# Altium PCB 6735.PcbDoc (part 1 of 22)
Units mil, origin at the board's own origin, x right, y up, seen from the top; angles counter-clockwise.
Board outline 2641.73 x 5165.35 mil, 6 copper layers (Top, Inner Layer 2, Inner Layer 3, Inner Layer 4, Inner Layer 5, Bottom), stack 35.7 mil thick; 1011 components, 790 nets, 4118 pads, 9325 vias.
Unrouted connection lines stored in the file: 4610.
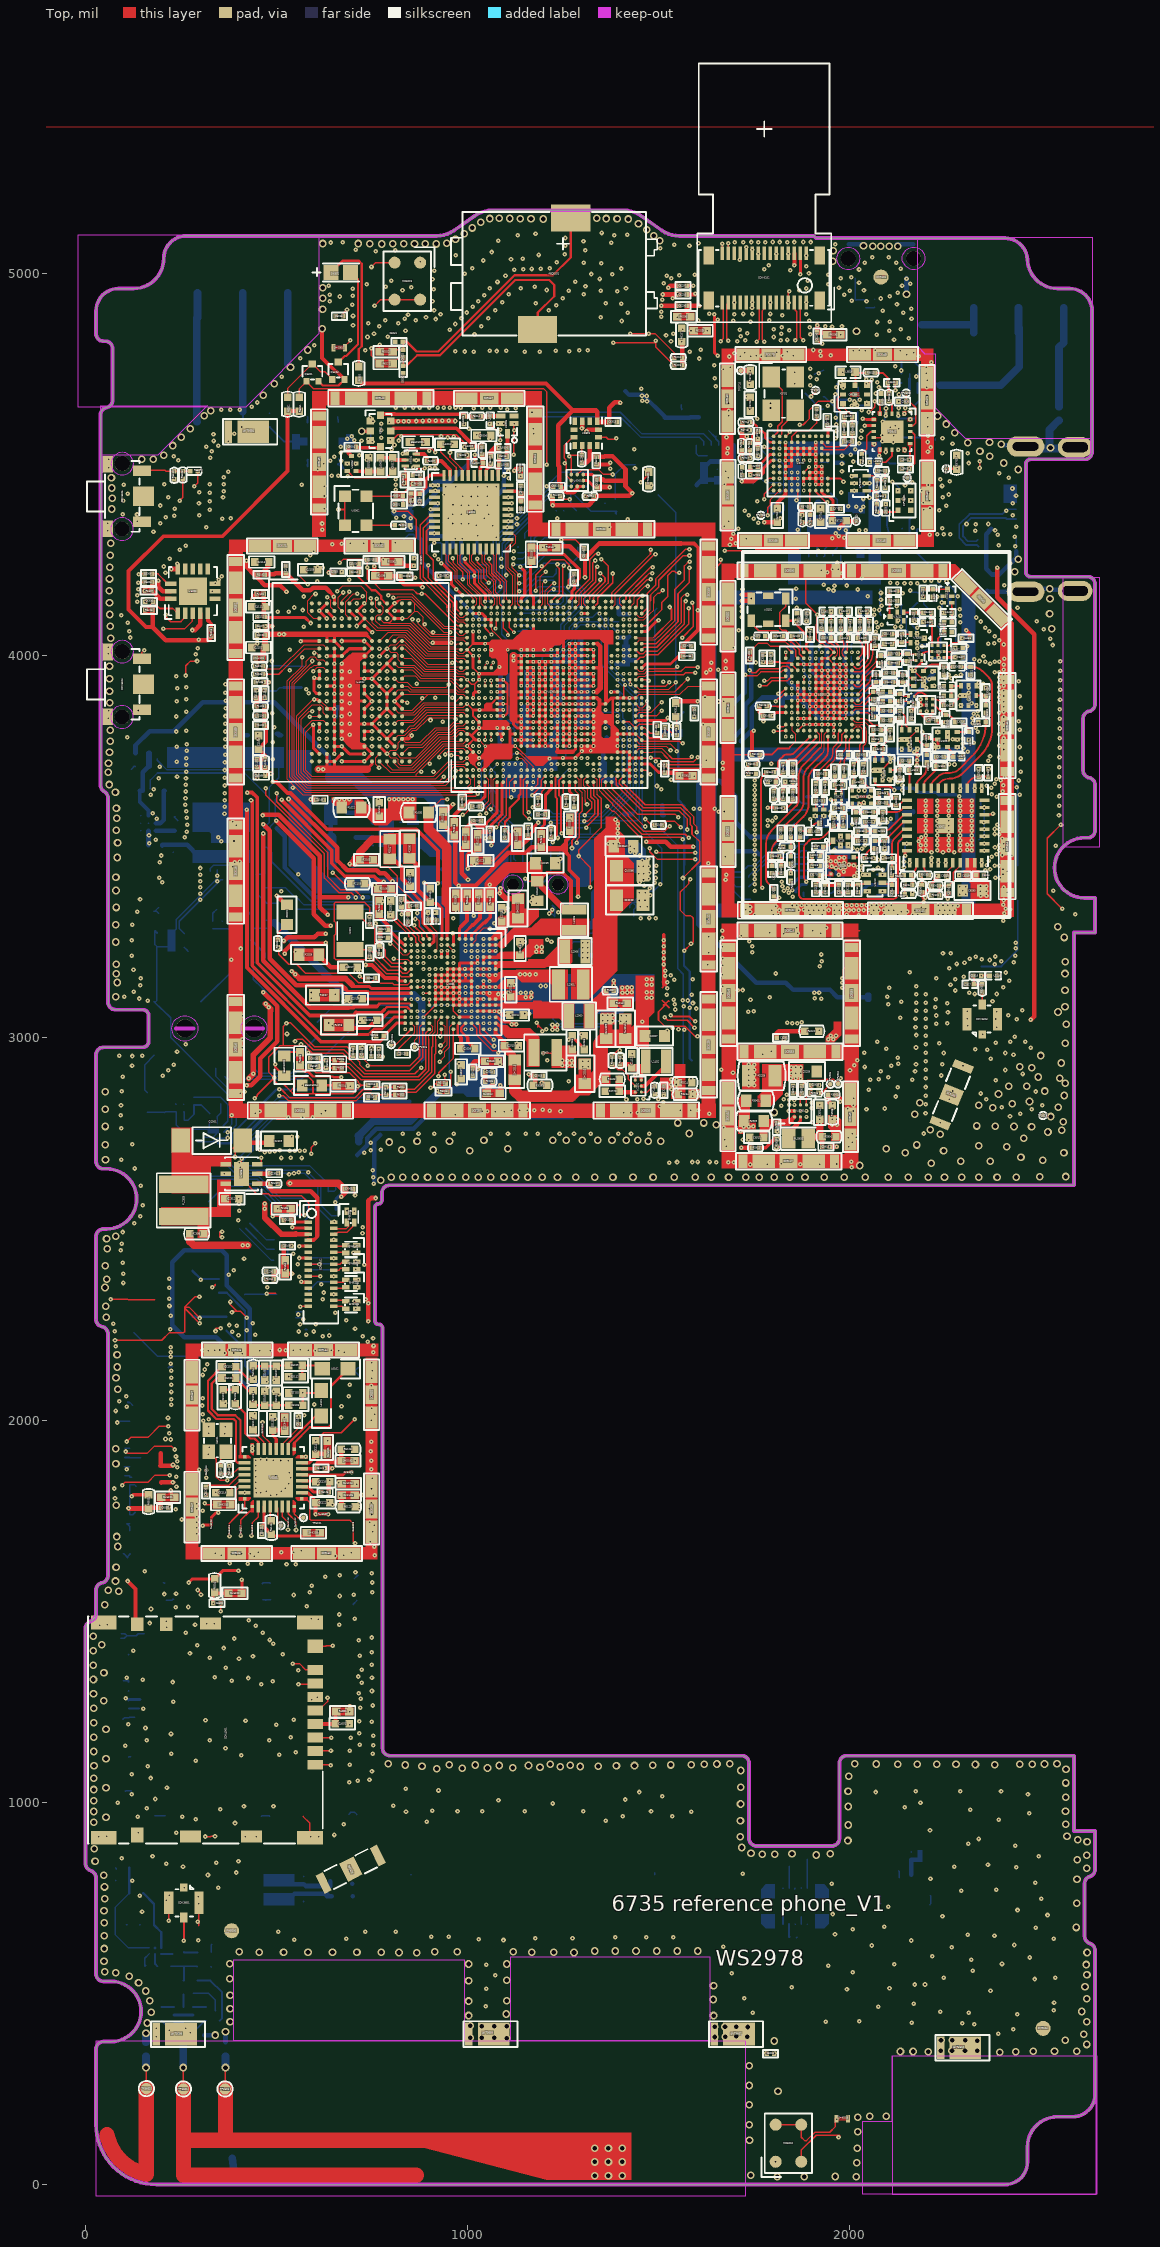
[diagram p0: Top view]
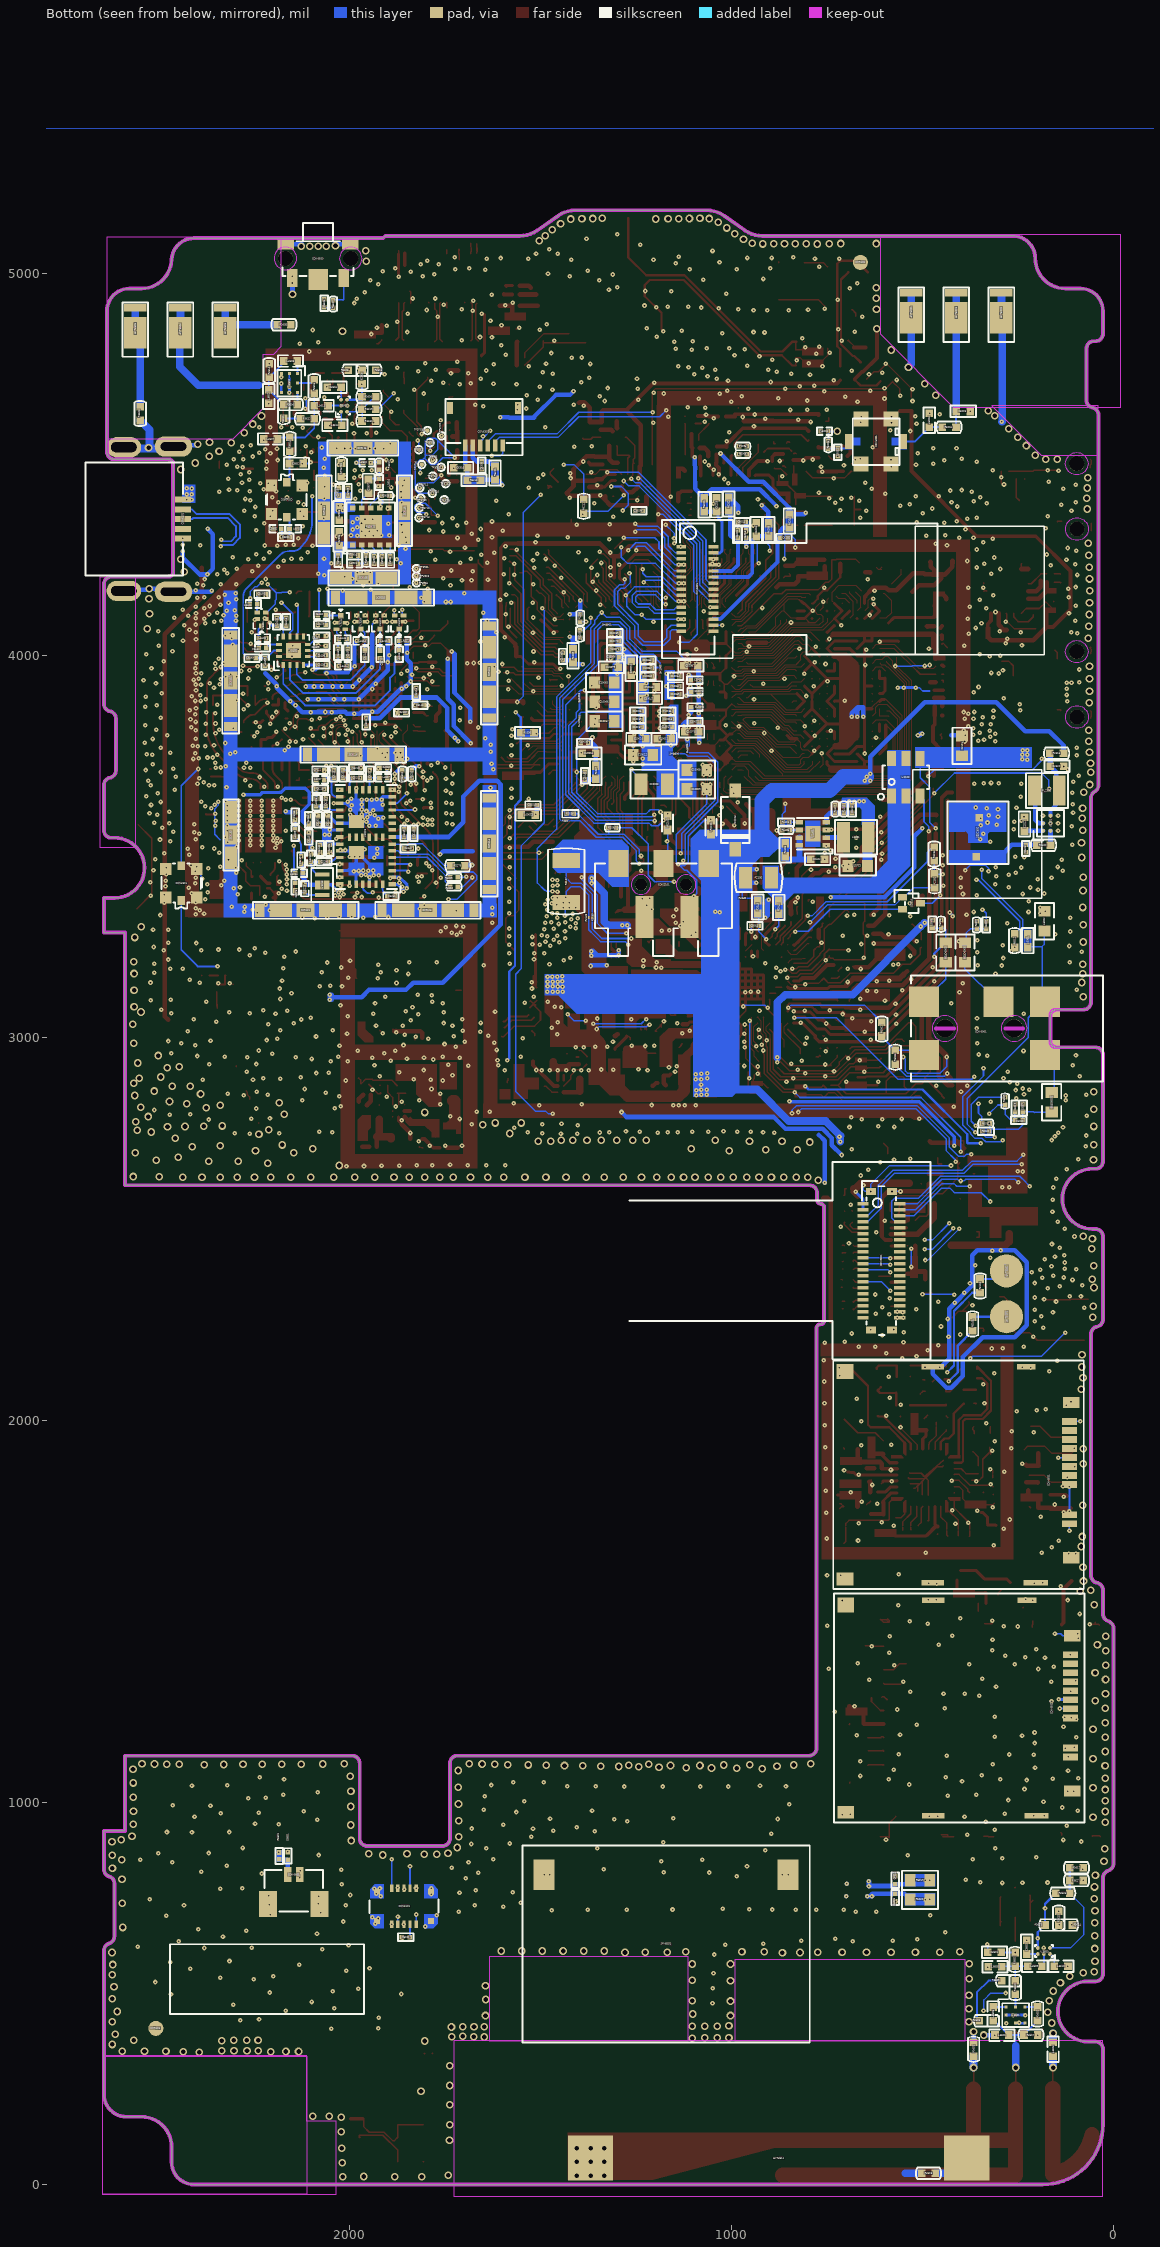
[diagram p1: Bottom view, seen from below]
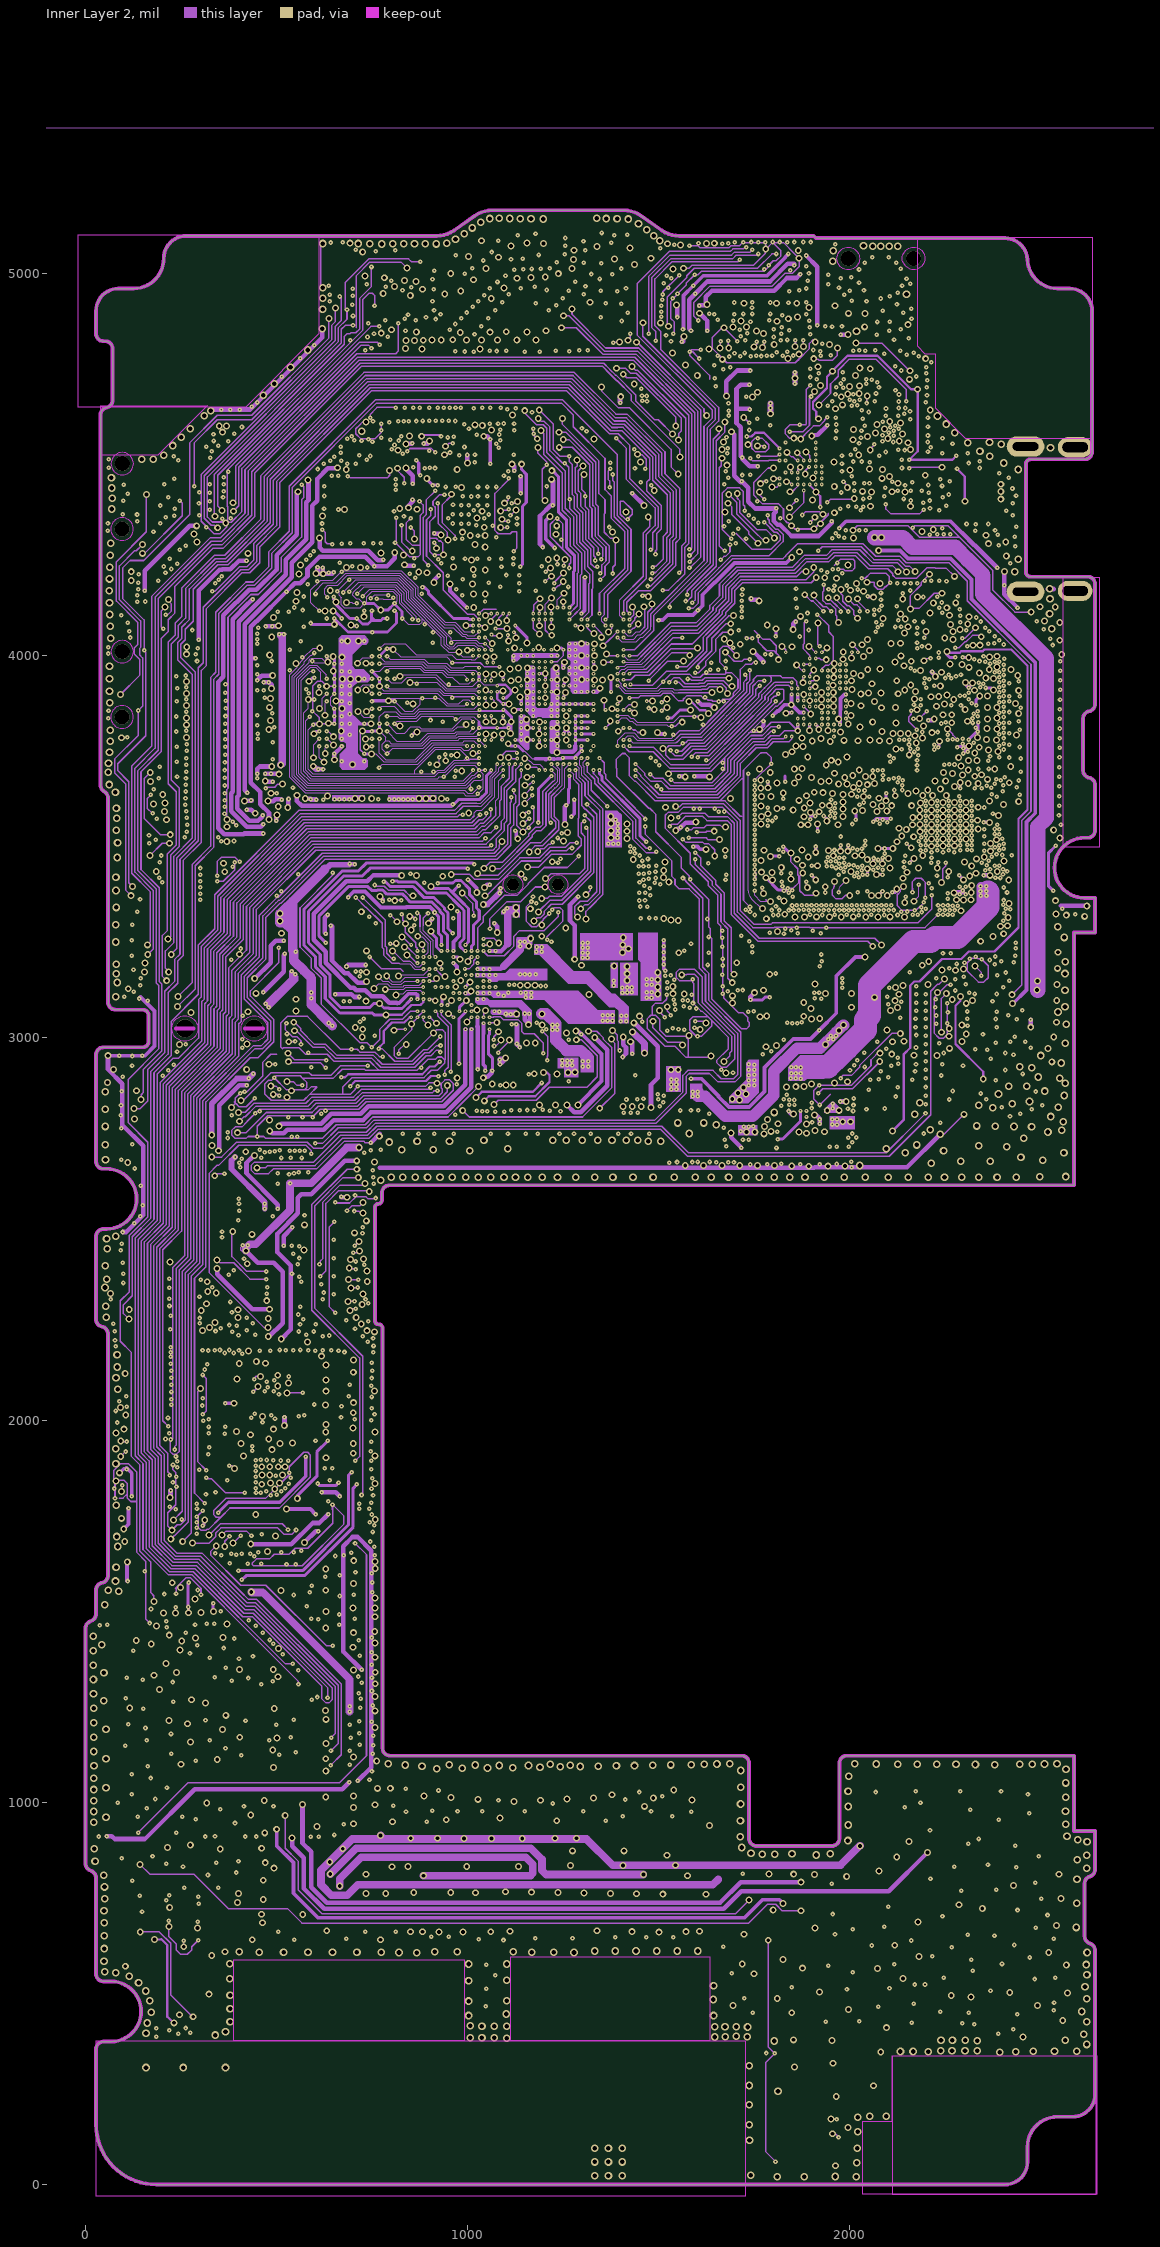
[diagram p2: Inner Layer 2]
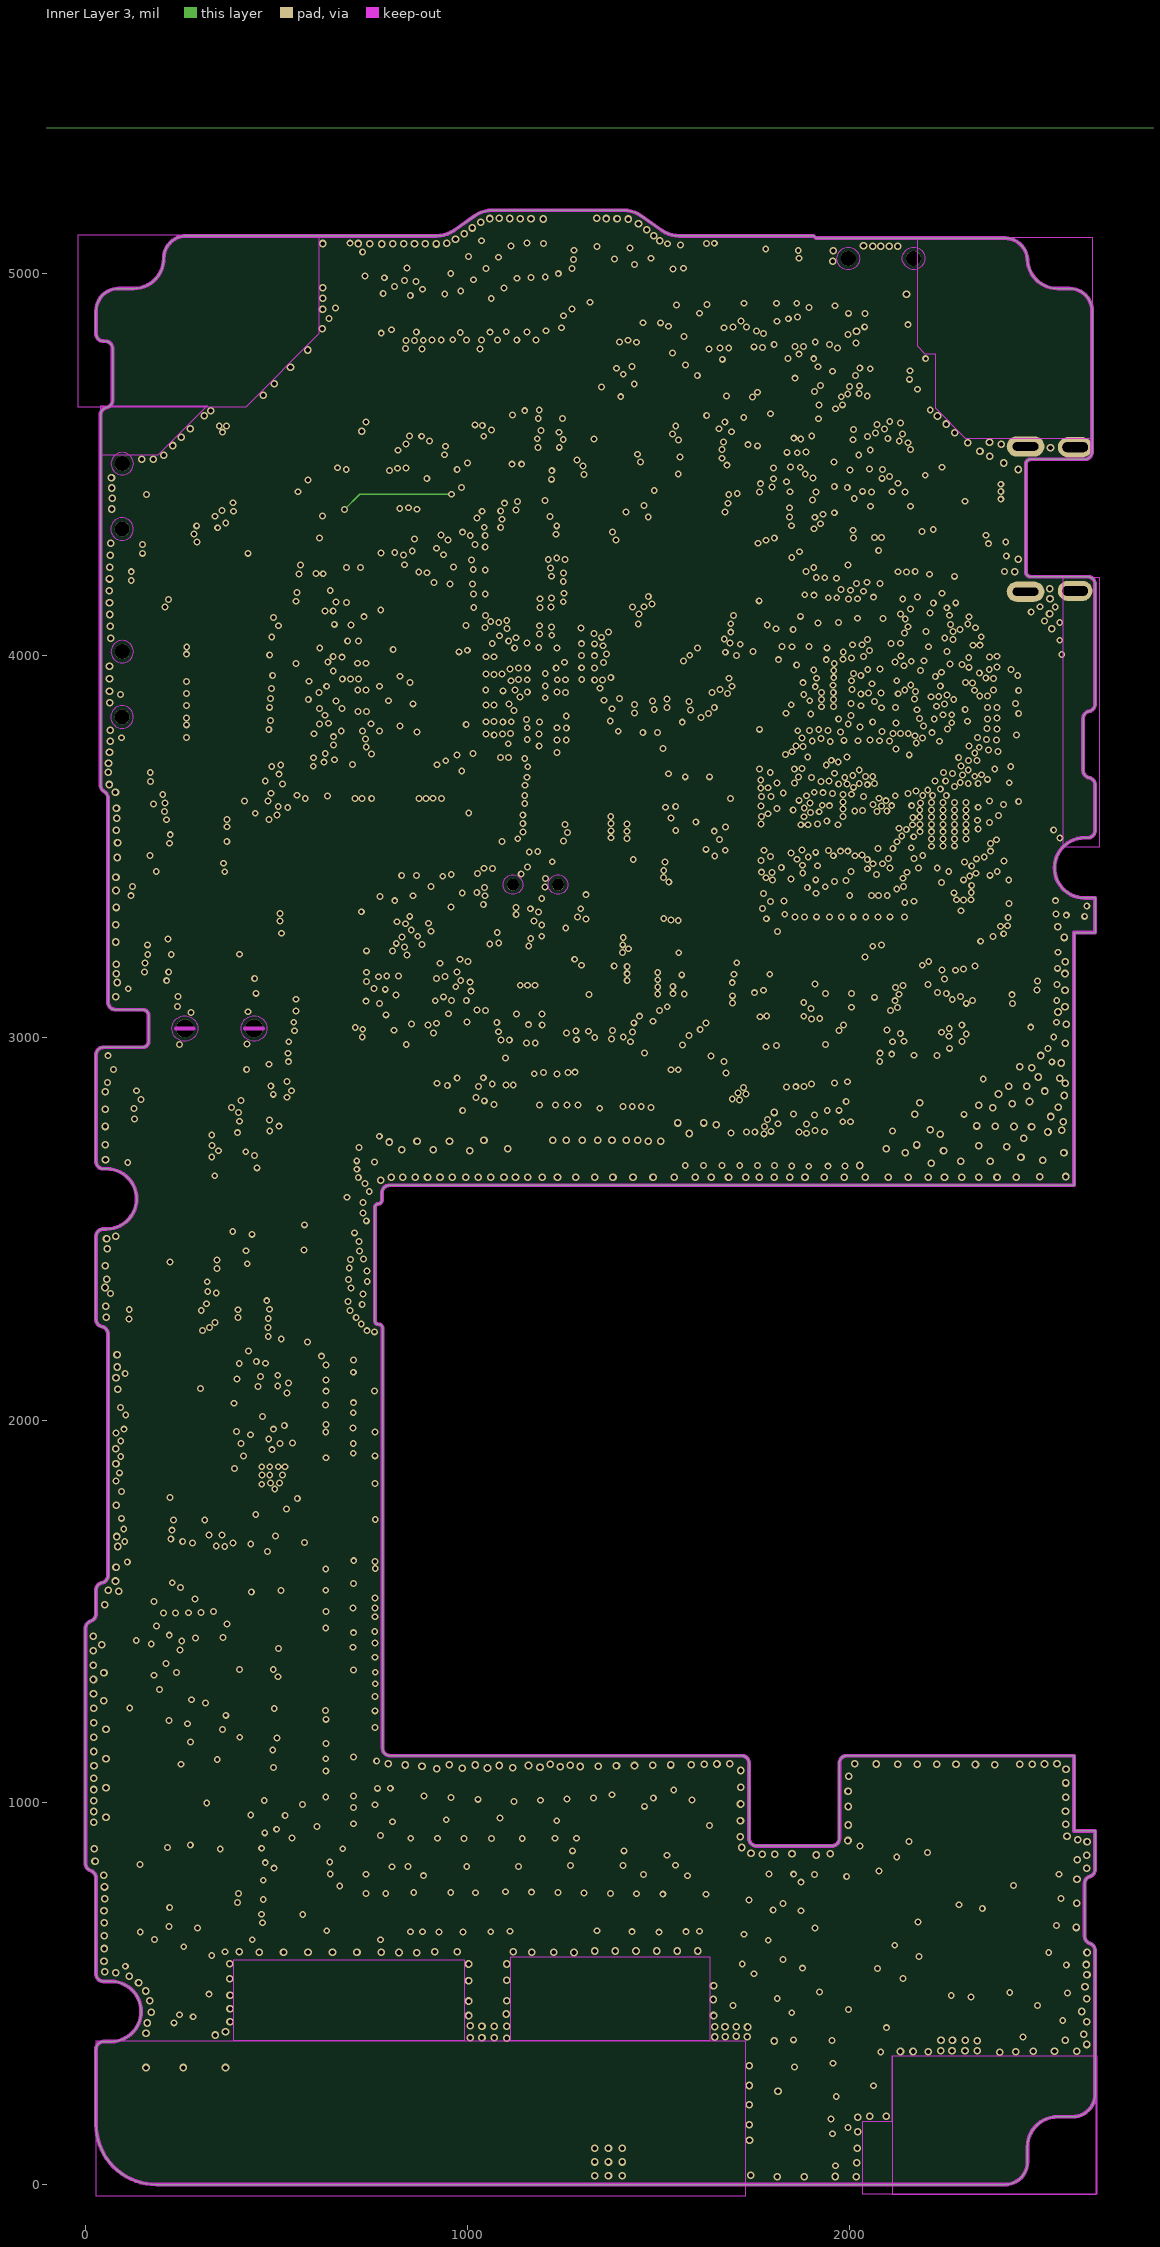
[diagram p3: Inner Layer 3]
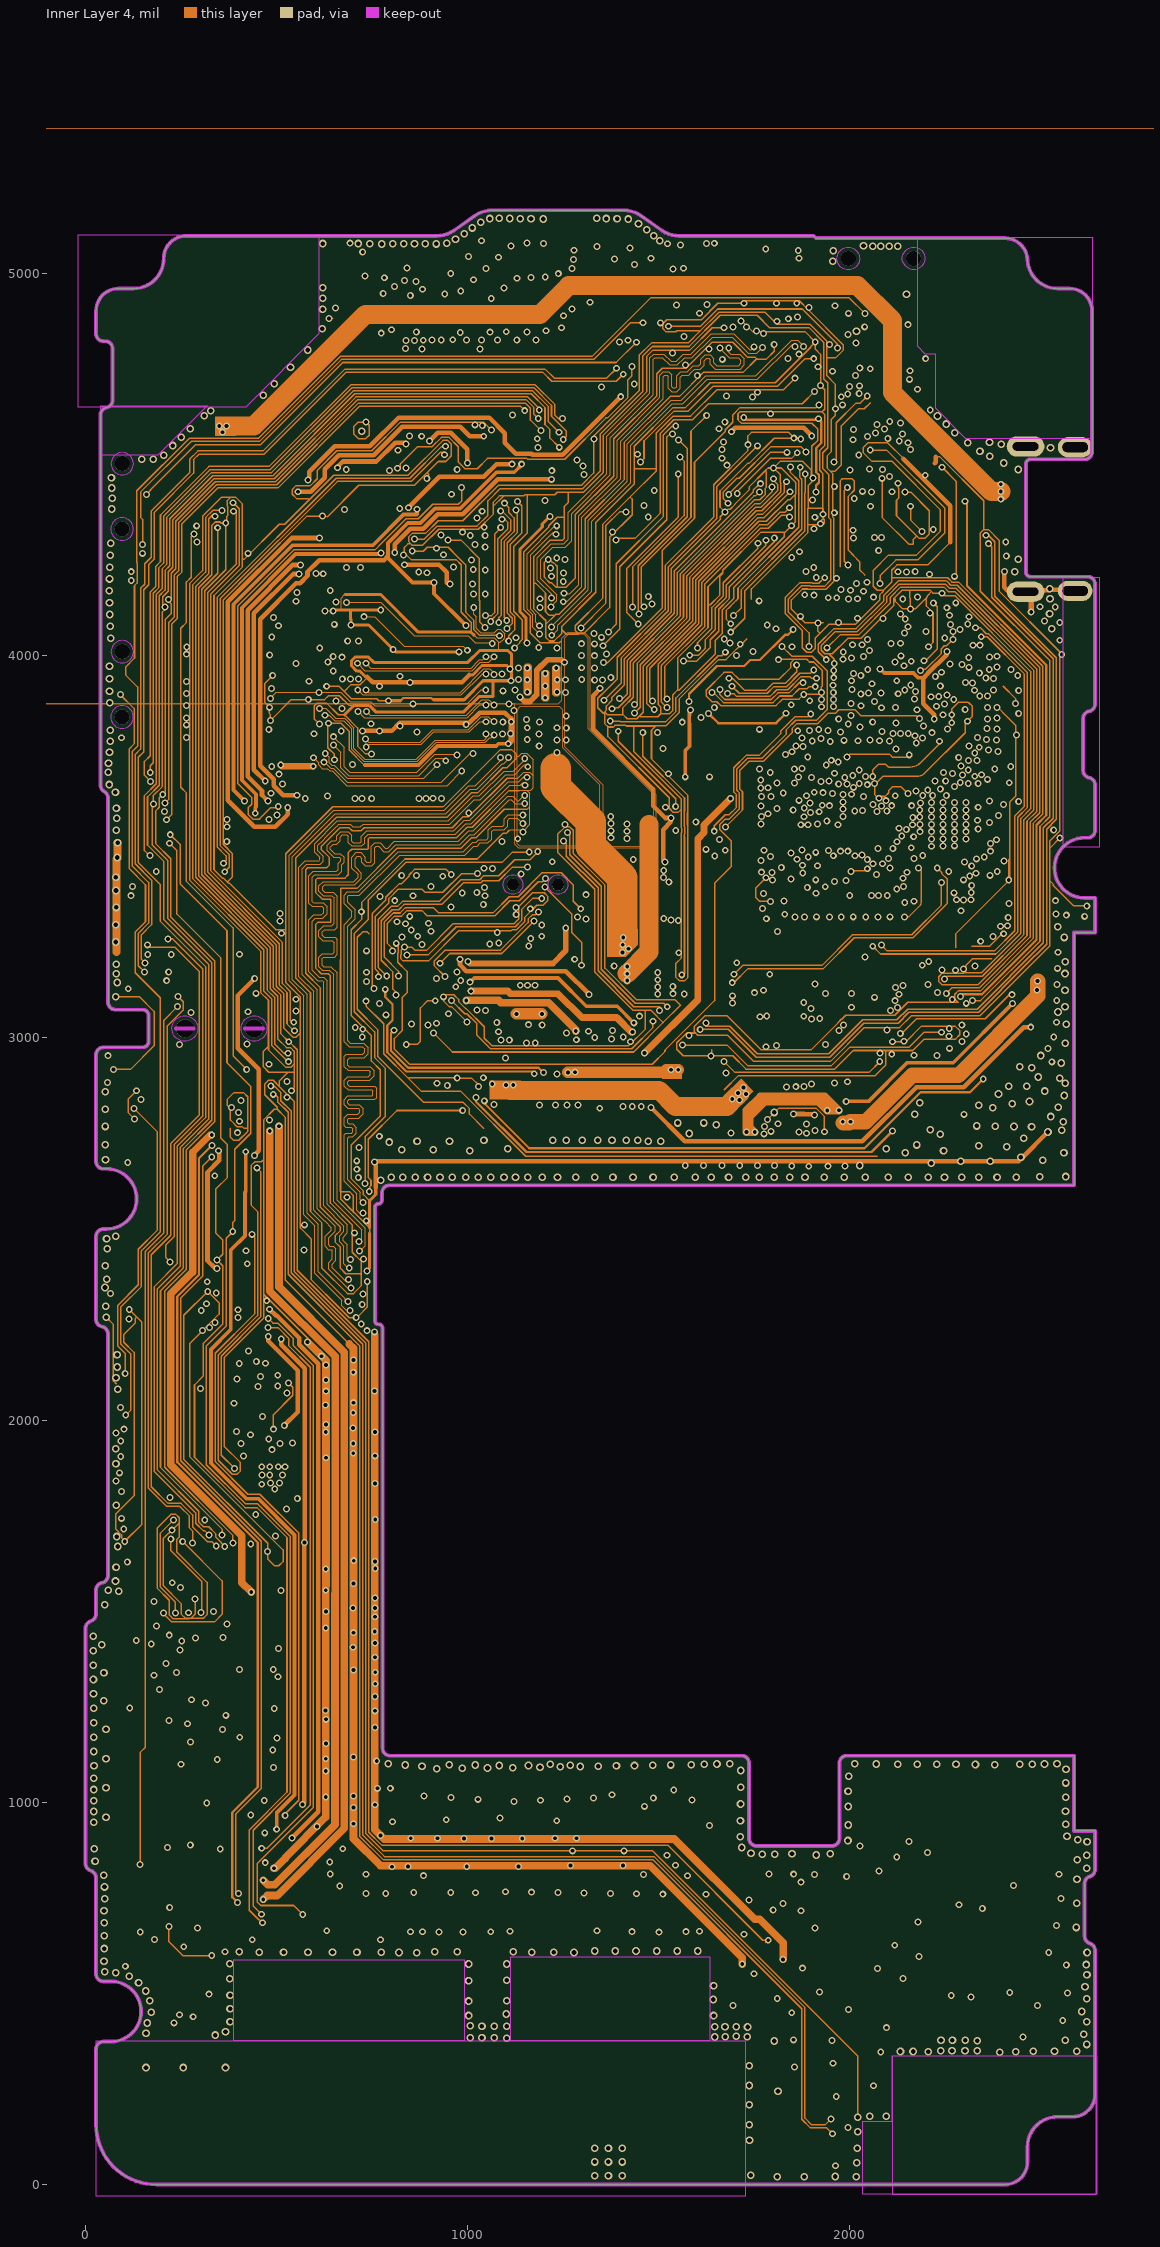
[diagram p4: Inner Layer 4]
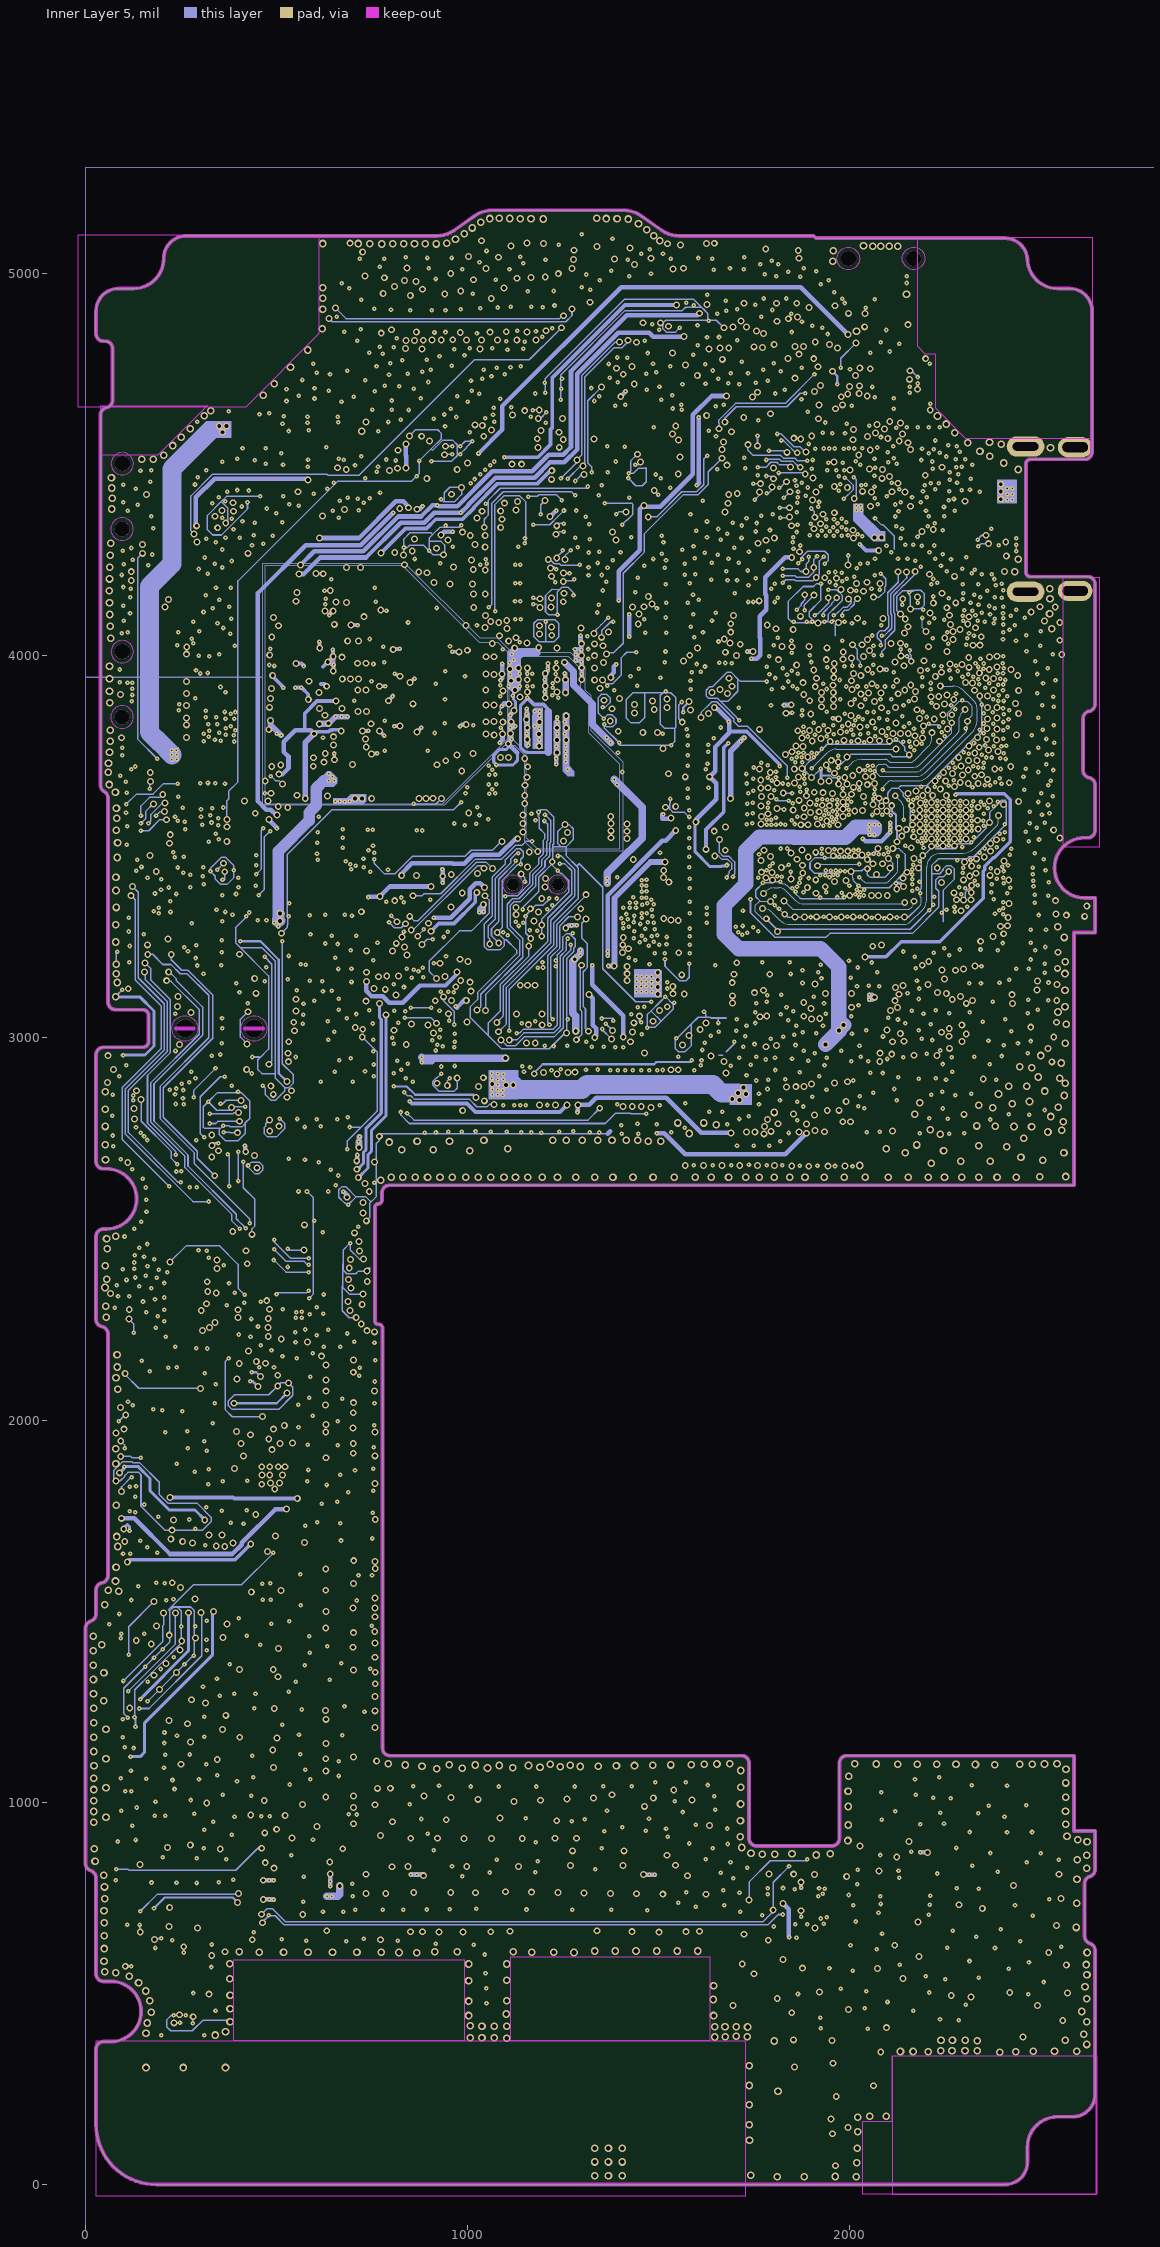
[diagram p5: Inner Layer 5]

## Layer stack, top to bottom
Solder Mask Top: solder mask 0.4, Solder Resist, Dk 3.5
Top: signal copper 0.7
Dielectric 1: dielectric 2.5, FR-4, Dk 4.2
Inner Layer 2: signal copper 1.4
Dielectric2: dielectric 7.7, FR-4, Dk 4.2
Inner Layer 3: signal copper 1.4
Dielectric3: dielectric 8.3, FR-4, Dk 4.2
Inner Layer 4: signal copper 1.4
Dielectric4: dielectric 7.7, FR-4, Dk 4.2
Inner Layer 5: signal copper 1.4
Dielectric5: dielectric 2.5, FR-4, Dk 4.2
Bottom: signal copper 0.7
Solder Mask Bottom: solder mask 0.4, Solder Resist, Dk 3.5

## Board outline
2627.95,630.83 2627.97,630.83 cw(c2622.05,612.05) 2641.73,612.05 2641.73,236.22 cw(c2582.68,236.22) 2582.68,177.17 2543.31,177.17 ccw(c2543.31,98.43) 2464.57,98.43 2464.57,59.06 cw(c2405.51,59.06) 2405.51,0 185.04,0 cw(c185.04,157.48) 27.56,157.48 27.56,354.33 cw(c47.24,354.33) 47.24,374.02 66.93,374.02 ccw(c66.93,452.76) 66.93,531.5 47.24,531.5 cw(c47.24,551.18) 27.56,551.18 27.56,802.42 ccw(c7.87,802.42) 16.19,820.26 11.37,822.51 cw(c19.68,840.35) 0,840.35 0,1455.18 cw(c19.69,1455.18) 11.37,1473.02 16.19,1475.27 ccw(c7.87,1493.11) 27.56,1493.11 27.56,1555.12 cw(c47.24,1555.12) 43.31,1574.41 43.29,1574.4 ccw(c39.37,1593.69) 59.06,1593.69 59.06,2225.21 ccw(c39.37,2225.21) 43.31,2244.49 43.32,2244.49 cw(c47.24,2263.78) 27.56,2263.78 27.56,2480.32 cw(c47.24,2480.32) 47.24,2500 55.12,2500 ccw(c55.12,2578.74) 55.12,2657.48 47.24,2657.48 cw(c47.24,2677.17) 27.56,2677.17 27.56,2955.72 cw(c47.25,2955.72) 47.24,2975.41 149.61,2975.41 ccw(c149.61,2991.15) 165.35,2991.15 165.35,3058.08 ccw(c149.61,3058.08) 149.61,3073.83 78.74,3073.83 cw(c78.74,3093.52) 59.06,3093.52 59.06,3627.32 ccw(c39.37,3627.32) 49.21,3644.37 cw(c59.06,3661.42) 39.37,3661.42 39.37,4629.92 cw(c59.06,4629.92) 55.12,4649.21 55.11,4649.21 ccw(c51.18,4668.5) 70.87,4668.5 70.87,4803.15 ccw(c51.18,4803.15) 51.18,4822.84 47.24,4822.84 cw(c47.24,4842.52) 27.56,4842.52 27.56,4901.58 cw(c86.61,4901.58) 86.61,4960.63 125.98,4960.63 ccw(c125.98,5039.37) 204.72,5039.37 cw(c263.78,5039.37) 263.78,5098.43 918.96,5098.43 ccw(c918.96,5177.17) 964.12,5112.67 1019.03,5151.12 cw(c1064.2,5086.62) 1064.2,5165.36 1408.24,5165.36 cw(c1408.24,5086.62) 1453.41,5151.12 1508.32,5112.67 ccw(c1553.48,5177.17) 1553.48,5098.43 1905.51,5098.43 1911.42,5092.52 2405.64,5092.52 cw(c2405.64,5033.47) 2464.64,5036 2464.64,5035.94 ccw(c2543.31,5039.37) 2543.31,4960.63 2574.8,4960.63 cw(c2574.8,4901.58) 2633.86,4901.58 2633.86,4533.47 cw(c2614.17,4533.47) 2614.17,4513.78 2472.44,4513.78 ccw(c2472.44,4501.97) 2460.63,4501.97 2460.63,4218.51 ccw(c2472.44,4218.51) 2472.44,4206.69 2622.05,4206.69 cw(c2622.05,4187.01) 2641.73,4187.01 2641.73,3874.02 cw(c2622.05,3874.02) 2625.98,3854.73 2626,3854.73 ccw(c2629.92,3835.44) 2610.24,3835.44 2610.24,3699.99 ccw(c2629.92,3699.99) 2625.98,3680.71 2625.97,3680.71 cw(c2622.05,3661.42) 2641.73,3661.42 2641.73,3543.31 cw(c2622.05,3543.31) 2622.05,3523.62 2614.17,3523.62 ccw(c2614.17,3444.88) 2614.17,3366.14 2641.73,3366.14 2641.73,3275.59 2586.61,3275.59 2586.61,2614.3 795.28,2614.3 ccw(c795.28,2594.61) 775.59,2594.61 775.59,2575.63 cw(c765.75,2575.63) 765.75,2565.79 ccw(c766.45,2556.65) 757.31,2555.95 757.31,2260.67 ccw(c766.45,2259.97) 765.75,2250.83 cw(c766.61,2240.13) 777.31,2240.99 777.31,1141.68 ccw(c797.02,1141.75) 796.66,1122.05 1716.54,1122.05 cw(c1716.54,1102.36) 1736.22,1102.36 1736.22,905.51 ccw(c1755.91,905.51) 1755.91,885.83 1952.76,885.83 ccw(c1952.76,905.51) 1972.44,905.51 1972.44,1102.36 cw(c1992.13,1102.36) 1992.13,1122.05 2586.61,1122.05 2586.61,925.2 2641.73,925.2 2641.73,824.96 cw(c2622.05,824.96) 2627.95,806.18 ccw(c2633.87,787.4) 2614.17,787.4 2614.17,649.61 ccw(c2633.86,649.61)

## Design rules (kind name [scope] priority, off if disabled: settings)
Clearance "Clearance - Net - D_GND - 100OHM" [InNet('D_GND') vs InNetClass('100OHM')] p1: gap=5 ignorepadtopadclearanceinfootprint=FALSE except(0: Arc-Hole Track-Hole SMDPad-Hole THPad-Hole Via-Hole Fill-Hole Poly-Hole Region-Hole Text-Hole; 4: Arc-Arc Arc-Track Arc-SMDPad Arc-THPad Arc-Via Track-Track Track-SMDPad Track-THPad Track-Via SMDPad-THPad SMDPad-Via THPad-THPad THPad-Via Via-Via; 7: SMDPad-SMDPad; 10: Arc-Text Track-Text SMDPad-Text THPad-Text Via-Text Fill-Text Poly-Text Region-Text Text-Text)
Clearance "Clearance - Net - D_GND - 90OHM_1" [InNet('D_GND') And OnLayer('Top') vs InNetClass('90OHM') And OnLayer('Top')] p2: gap=10 ignorepadtopadclearanceinfootprint=FALSE except(0: Arc-Hole Track-Hole SMDPad-Hole THPad-Hole Via-Hole Fill-Hole Poly-Hole Region-Hole Text-Hole; 4: Arc-SMDPad Arc-THPad Arc-Via Track-SMDPad Track-THPad Track-Via SMDPad-THPad SMDPad-Via THPad-THPad THPad-Via Via-Via; 7: SMDPad-SMDPad)
Clearance "Clearance - Net - D_GND - 90OHM_2" [InNet('D_GND') vs InNetClass('90OHM')] p3: gap=4 ignorepadtopadclearanceinfootprint=FALSE except(0: Arc-Hole Track-Hole SMDPad-Hole THPad-Hole Via-Hole Fill-Hole Poly-Hole Region-Hole Text-Hole; 5: Arc-Arc Arc-Track Track-Track; 6: SMDPad-Fill SMDPad-Poly SMDPad-Region THPad-Fill THPad-Poly THPad-Region Fill-Fill Fill-Poly Fill-Region Poly-Poly Poly-Region Region-Region; 7: SMDPad-SMDPad; 10: Arc-Text Track-Text SMDPad-Text THPad-Text Via-Text Fill-Text Poly-Text Region-Text Text-Text)
Clearance "Clearance - Net - D_GND - 100OHM_1" [InNet('D_GND') And OnLayer('Bottom') vs InNetClass('100OHM') And OnLayer('Bottom')] p4: gap=8 ignorepadtopadclearanceinfootprint=FALSE except(0: Arc-Hole Track-Hole SMDPad-Hole THPad-Hole Via-Hole Fill-Hole Poly-Hole Region-Hole Text-Hole; 4: Arc-SMDPad Arc-THPad Arc-Via Track-SMDPad Track-THPad Track-Via SMDPad-THPad SMDPad-Via THPad-THPad THPad-Via Via-Via; 7: SMDPad-SMDPad; 10: Arc-Text Track-Text SMDPad-Text THPad-Text Via-Text Fill-Text Poly-Text Region-Text Text-Text)
Clearance "Clearance - Net - D_GND - 90OHM_3" [InNet('D_GND') And OnLayer('Inner Layer 4') vs InNetClass('90OHM') And OnLayer('Inner Layer 4')] p5: gap=5 ignorepadtopadclearanceinfootprint=FALSE except(0: Arc-Hole Track-Hole SMDPad-Hole THPad-Hole Via-Hole Fill-Hole Poly-Hole Region-Hole Text-Hole; 4: Arc-SMDPad Arc-THPad Arc-Via Track-SMDPad Track-THPad Track-Via SMDPad-THPad SMDPad-Via THPad-THPad THPad-Via Via-Via; 7: SMDPad-SMDPad; 10: Arc-Text Track-Text SMDPad-Text THPad-Text Via-Text Fill-Text Poly-Text Region-Text Text-Text)
Clearance "Clearance - Net - D_GND - 90OHM" [InNet('D_GND') And OnLayer('Bottom') vs InNetClass('90OHM') And OnLayer('Bottom')] p6: gap=10 ignorepadtopadclearanceinfootprint=FALSE except(0: Arc-Hole Track-Hole SMDPad-Hole THPad-Hole Via-Hole Fill-Hole Poly-Hole Region-Hole Text-Hole; 4: Arc-SMDPad Arc-THPad Arc-Via Track-SMDPad Track-THPad Track-Via SMDPad-THPad SMDPad-Via THPad-THPad THPad-Via Via-Via; 7: SMDPad-SMDPad)
Clearance "Clearance - Net - D_GND - 50OHM_2" [InNet('D_GND') And OnLayer('Inner Layer 2') vs InNetClass('50OHM') And OnLayer('Inner Layer 2')] p7: gap=9 ignorepadtopadclearanceinfootprint=FALSE except(0: Arc-Hole Track-Hole SMDPad-Hole THPad-Hole Via-Hole Fill-Hole Poly-Hole Region-Hole Text-Hole; 4: Arc-THPad Arc-Via Track-THPad Track-Via SMDPad-THPad THPad-THPad THPad-Via Via-Via Via-Fill Via-Poly Via-Region; 6: SMDPad-Fill SMDPad-Poly SMDPad-Region THPad-Fill THPad-Poly THPad-Region Fill-Fill Fill-Poly Fill-Region Poly-Poly Poly-Region Region-Region; 7: SMDPad-SMDPad; 10: Arc-Text Track-Text SMDPad-Text THPad-Text Via-Text Fill-Text Poly-Text Region-Text Text-Text)
Clearance "Clearance - Net - D_GND - 50OHM_3" [InNet('D_GND') And OnLayer('Inner Layer 5') vs InNetClass('50OHM') And OnLayer('Inner Layer 5')] p8: gap=9 ignorepadtopadclearanceinfootprint=FALSE except(0: Arc-Hole Track-Hole SMDPad-Hole THPad-Hole Via-Hole Fill-Hole Poly-Hole Region-Hole Text-Hole; 4: Arc-THPad Arc-Via Track-THPad Track-Via SMDPad-THPad THPad-THPad THPad-Via; 7: SMDPad-SMDPad; 10: Arc-Text Track-Text SMDPad-Text THPad-Text Via-Text Fill-Text Poly-Text Region-Text Text-Text)
Clearance "Clearance - Net - D_GND - 50OHM_1" [InNet('D_GND') And OnLayer('Bottom') vs InNetClass('50OHM') And OnLayer('Bottom')] p9: gap=8 ignorepadtopadclearanceinfootprint=FALSE except(0: Arc-Hole Track-Hole SMDPad-Hole THPad-Hole Via-Hole Fill-Hole Poly-Hole Region-Hole Text-Hole; 4: SMDPad-THPad THPad-THPad; 7: SMDPad-SMDPad; 10: Arc-Text Track-Text SMDPad-Text THPad-Text Via-Text Fill-Text Poly-Text Region-Text Text-Text)
Clearance "Clearance - Net - D_GND - 50OHM" [InNet('D_GND') And OnLayer('Top') vs InNetClass('50OHM') And OnLayer('Top')] p10: gap=8 ignorepadtopadclearanceinfootprint=FALSE except(0: Arc-Hole Track-Hole SMDPad-Hole THPad-Hole Via-Hole Fill-Hole Poly-Hole Region-Hole Text-Hole; 4: SMDPad-THPad THPad-THPad; 7: SMDPad-SMDPad; 10: Arc-Text Track-Text SMDPad-Text THPad-Text Via-Text Fill-Text Poly-Text Region-Text Text-Text)
Clearance "Clearance - NetClass - 50OHM" [InNetClass('50OHM') And OnLayer('Inner Layer 4')] p11: gap=7 ignorepadtopadclearanceinfootprint=FALSE except(0: Arc-Hole Track-Hole SMDPad-Hole THPad-Hole Via-Hole Fill-Hole Poly-Hole Region-Hole Text-Hole; 4: Arc-SMDPad Arc-THPad Arc-Text Track-SMDPad Track-THPad Track-Text SMDPad-THPad SMDPad-Via SMDPad-Text THPad-THPad THPad-Via THPad-Text Via-Via Via-Text Fill-Text Poly-Text Region-Text; 10: Text-Text)
Clearance "Clearance - NetClass - 100OHM_2" [InNetClass('100OHM') And OnLayer('Inner Layer 4')] p12: gap=5 ignorepadtopadclearanceinfootprint=FALSE except(0: Arc-Hole Track-Hole SMDPad-Hole THPad-Hole Via-Hole Fill-Hole Poly-Hole Region-Hole Text-Hole; 4: Arc-SMDPad Arc-THPad Arc-Text Track-SMDPad Track-THPad Track-Text SMDPad-THPad SMDPad-Via SMDPad-Text THPad-THPad THPad-Via THPad-Text Via-Via Via-Text Fill-Text Poly-Text Region-Text; 6: Arc-Arc Arc-Track Arc-Via Track-Track Track-Via; 7: SMDPad-SMDPad; 10: Text-Text)
Clearance "Clearance - NetClass - 90OHM" [InNetClass('90OHM') And OnLayer('Top')] p13: gap=5 ignorepadtopadclearanceinfootprint=FALSE except(0: Arc-Hole Track-Hole SMDPad-Hole THPad-Hole Via-Hole Fill-Hole Poly-Hole Region-Hole Text-Hole; 4: Arc-SMDPad Arc-THPad Arc-Via Arc-Text Track-SMDPad Track-THPad Track-Via Track-Text SMDPad-THPad SMDPad-Via SMDPad-Text THPad-THPad THPad-Via THPad-Text Via-Via Via-Text Fill-Text Poly-Text Region-Text; 7: SMDPad-SMDPad; 10: Text-Text)
Clearance "Clearance - NetClass - 100OHM" [InNetClass('100OHM') OR InNetClass('50OHM')] p14: gap=4 ignorepadtopadclearanceinfootprint=FALSE except(0: Arc-Hole Track-Hole SMDPad-Hole THPad-Hole Via-Hole Fill-Hole Poly-Hole Region-Hole Text-Hole; 6: SMDPad-Fill SMDPad-Poly SMDPad-Region THPad-Fill THPad-Poly THPad-Region Fill-Fill Fill-Poly Fill-Region Poly-Poly Poly-Region Region-Region; 7: SMDPad-SMDPad; 10: Text-Text)
Clearance "Clearance - NetClass - RF50(L3)" [InNetClass('RF50(L3)') And OnLayer('Top') OR InNetClass('RF50(L3)') And OnLayer('Bottom')] p15: gap=5 ignorepadtopadclearanceinfootprint=FALSE except(0: Arc-Hole Track-Hole SMDPad-Hole THPad-Hole Via-Hole Fill-Hole Poly-Hole Region-Hole Text-Hole; 4: Arc-SMDPad Arc-THPad Arc-Via Arc-Text Track-SMDPad Track-THPad Track-Via Track-Text SMDPad-SMDPad SMDPad-THPad SMDPad-Via SMDPad-Text THPad-THPad THPad-Via THPad-Text Via-Via Via-Text Fill-Text Poly-Text Region-Text; 10: Text-Text)
Clearance "Clearance - NetClass - 90OHM_1" [InNetClass('90OHM') And OnLayer('Inner Layer 4')] p16: gap=5 ignorepadtopadclearanceinfootprint=FALSE except(0: Arc-Hole Track-Hole SMDPad-Hole THPad-Hole Via-Hole Fill-Hole Poly-Hole Region-Hole Text-Hole; 4: Arc-SMDPad Arc-THPad Arc-Text Track-SMDPad Track-THPad Track-Text SMDPad-THPad SMDPad-Via SMDPad-Text THPad-THPad THPad-Via THPad-Text Via-Via Via-Text Fill-Text Poly-Text Region-Text; 7: SMDPad-SMDPad; 10: Text-Text)
Clearance "Clearance - NetClass - 100OHM_1" [InNetClass('100OHM') And OnLayer('Top') OR InNetClass('100OHM') And OnLayer('Bottom')] p17: gap=8 ignorepadtopadclearanceinfootprint=FALSE except(0: Arc-Hole Track-Hole SMDPad-Hole THPad-Hole Via-Hole Fill-Hole Poly-Hole Region-Hole Text-Hole; 4: Arc-Text Track-Text SMDPad-THPad SMDPad-Via SMDPad-Text THPad-THPad THPad-Via THPad-Text Via-Via Via-Text Fill-Text Poly-Text Region-Text; 5: Arc-Arc Arc-Track Arc-SMDPad Arc-THPad Arc-Via Track-Track Track-SMDPad Track-THPad Track-Via; 7: SMDPad-SMDPad; 10: Text-Text)
Clearance "Clearance - NetClass - 90OHM_2" [InNetClass('90OHM') And OnLayer('Bottom')] p18: gap=5 ignorepadtopadclearanceinfootprint=FALSE except(0: Arc-Hole Track-Hole SMDPad-Hole THPad-Hole Via-Hole Fill-Hole Poly-Hole Region-Hole Text-Hole; 4: Arc-Text Track-Text SMDPad-THPad SMDPad-Via SMDPad-Text THPad-THPad THPad-Via THPad-Text Via-Via Via-Text Fill-Text Poly-Text Region-Text; 7: SMDPad-SMDPad; 10: Text-Text)
Clearance "Clearance - NetClass - 50OHM_2" [InNetClass('50OHM') And OnLayer('Bottom')] p19: gap=10 ignorepadtopadclearanceinfootprint=FALSE except(0: Arc-Hole Track-Hole SMDPad-Hole THPad-Hole Via-Hole Fill-Hole Poly-Hole Region-Hole Text-Hole; 4: Arc-Text Track-Text SMDPad-THPad SMDPad-Via SMDPad-Text THPad-THPad THPad-Via THPad-Text Via-Via Via-Text Fill-Text Poly-Text Region-Text; 7: SMDPad-SMDPad; 8: Arc-Arc Arc-Track Arc-SMDPad Arc-THPad Arc-Via Track-Track Track-SMDPad Track-THPad Track-Via)
Clearance "Clearance - NetClass - 50OHM_3" [InNetClass('50OHM') And OnLayer('Inner Layer 2') OR InNetClass('50OHM') And OnLayer('Inner Layer 5')] p20: gap=9 ignorepadtopadclearanceinfootprint=FALSE except(0: Arc-Hole Track-Hole SMDPad-Hole THPad-Hole Via-Hole Fill-Hole Poly-Hole Region-Hole Text-Hole; 4: Arc-SMDPad Arc-THPad Arc-Via Arc-Text Track-SMDPad Track-THPad Track-Via Track-Text SMDPad-THPad SMDPad-Via SMDPad-Text THPad-THPad THPad-Via THPad-Text Via-Via Via-Text Fill-Text Poly-Text Region-Text; 7: SMDPad-SMDPad; 10: Text-Text)
Clearance "Clearance - NetClass - 50OHM_1" [InNetClass('50OHM') And OnLayer('Top')] p21: gap=8 ignorepadtopadclearanceinfootprint=FALSE except(0: Arc-Hole Track-Hole SMDPad-Hole THPad-Hole Via-Hole Fill-Hole Poly-Hole Region-Hole Text-Hole; 4: Arc-SMDPad Arc-THPad Arc-Text Track-SMDPad Track-THPad Track-Text SMDPad-THPad SMDPad-Via SMDPad-Text THPad-THPad THPad-Via THPad-Text Via-Via Via-Text Fill-Text Poly-Text Region-Text; 7: SMDPad-SMDPad; 10: Text-Text)
Clearance "Clearance - Default - DEFAULT - Via" [IsVia vs IsVia] p22: gap=0 ignorepadtopadclearanceinfootprint=FALSE
Clearance "Clearance - Default - DEFAULT- SMD" [IsVia vs IsSMTPin] p23: gap=2 ignorepadtopadclearanceinfootprint=FALSE except(0: Arc-Hole Track-Hole SMDPad-Hole THPad-Hole Via-Hole Fill-Hole Poly-Hole Region-Hole Text-Hole)
Clearance "Clearance - Default - DEFAULT - Net" [All] p24: gap=4 ignorepadtopadclearanceinfootprint=FALSE except(0: Arc-Hole Track-Hole SMDPad-Hole THPad-Hole Via-Hole Fill-Hole Poly-Hole Region-Hole Text-Hole; 6: SMDPad-Fill SMDPad-Poly SMDPad-Region THPad-Fill THPad-Poly THPad-Region Fill-Fill Fill-Poly Fill-Region Poly-Poly Poly-Region Region-Region; 10: Text-Text)
ComponentClearance "ComponentClearance - Default - DEFAULT" [All] p1: gap=0 collisioncheckmode=3 verticalgap=10 showdistances=FALSE
FanoutControl Fanout_SOIC [IsSOIC] p1: bgadir=Out bgaviamode=Centered fanoutstyle=Auto fanoutdirection=Alternating viagrid=1 // Fanout_SOIC (Default Rule)
FanoutControl Fanout_Small [(CompPinCount < 5)] p2: bgadir=Out bgaviamode=Centered fanoutstyle=Auto fanoutdirection=OutThenIn viagrid=1 // Fanout_Small (Default Rule)
FanoutControl Fanout_LCC [IsLCC] p3: bgadir=Out bgaviamode=Centered fanoutstyle=Auto fanoutdirection=Alternating viagrid=1 // Fanout_LCC (Default Rule)
FanoutControl Fanout_BGA [IsBGA] p4: bgadir=Out bgaviamode=Centered fanoutstyle=Auto fanoutdirection=Alternating viagrid=1 // Fanout_BGA (Default Rule)
HoleToHoleClearance "HoleToHoleClearance - Default - DEFAULT" [All] p1: gap=5 allowstackedmicrovias=TRUE
Length "Default Length" [All] p1: maxlimit=50000 minlimit=0
MaxMinImpedance "Default Impedance" [All] p1: minimum=50.00 maximum=150.0
ParallelSegment "Default Parallel Segment Adjasent" [All] p1: limit=1000 gap=200
ParallelSegment "Default Parallel Segment Same Layer" [All] p2: limit=1000 gap=200
PlaneConnect "Default PlaneConnect" [All] p1: planeconnectstyle=Relief reliefexpansion=20 reliefentries=0 reliefconductorwidth=20 reliefairgap=10
PolygonConnect "PolygonConnect - Default SMT" [IsSMTPin] p1: connectstyle=Direct reliefconductorwidth=8 reliefentries=4 polygonreliefangle="45 Angle" airgapwidth=10
PolygonConnect "PolygonConnect - Default Pad" [All] p2: connectstyle=Relief reliefconductorwidth=20 reliefentries=4 polygonreliefangle="45 Angle" airgapwidth=10
RoutingLayers "RoutingLayers - Default - DEFAULT" [All] p1: top layer_v5=TRUE mid layer 1_v5=TRUE mid layer 2_v5=TRUE mid layer 3_v5=TRUE mid layer 4_v5=TRUE bottom layer_v5=TRUE
RoutingPriority "RoutingPriority - Default - DEFAULT" [All] p1: routingpriority=3
RoutingTopology "Default Routing Topology" [All] p1: topology=Shortest
RoutingVias "RoutingVias - Net - Net & Net" [InNet('ADD1') OR InNet('ADD5') OR InNet('ADD6') OR InNet('C2K_ANTENNA') OR InNet('N15925478') OR InNet('N16931615') OR InNet('N16931617') OR InNet('N16931618') OR InNet('N16931625') OR InNet('N18263809') OR InNet('N19717773') OR InNet('N19780807') OR InNet('N19786985') OR InNet('N19787376') OR InNet('N19787407') OR InNet('N19789349') OR InNet('N19790693') OR InNet('N19790880') OR InNet('N19790902') OR InNet('N20607950') OR InNet('N47019540') OR InNet('N47019602') OR InNet('N48048238') OR InNet('N48113596') OR InNet('N48144087') OR InNet('N48144216') OR InNet('RCN') OR InNet('RCN_A') OR InNet('RCP') OR InNet('RCP_A') OR InNet('RDN0') OR InNet('RDN0_A') OR InNet('RDN1') OR InNet('RDN1_A') OR InNet('RDN2') OR InNet('RDN3') OR InNet('RDP0') OR InNet('RDP0_A') OR InNet('RDP1') OR InNet('RDP1_A') OR InNet('RDP2') OR InNet('RDP3') OR InNet('RF_ANT_DRX_SWITCH') OR InNet('RF_ANT_TRX_1') OR InNet('RF_ANT_TRX_2') OR InNet('RF_ANT_TRX_3') OR InNet('RF_ANT_TRX_4') OR InNet('RF_ANT_TRX_5') OR InNet('RF_ANT_TRX_ASM') OR InNet('RF_ANT_TRX_CARKIT') OR InNet('RF_ANT_TRX_TXM') OR InNet('RF_B1_DRX_MT6169_RFIN2_HB3') OR InNet('RF_B1_DRX_MT6169_RFIP2_HB3') OR InNet('RF_B1_DRX_SAW') OR InNet('RF_B1_DRX_SAW_RFIN2_HB1') OR InNet('RF_B1_DRX_SAW_RFIP2_HB1') OR InNet('RF_B1_DRX_SWITCH') OR InNet('RF_B1_PA_DPX') OR InNet('RF_B1_PA_PA') OR InNet('RF_B1_PRX_DPX_RFIN1') OR InNet('RF_B1_PRX_DPX_RFIP1') OR InNet('RF_B1_PRX_MT6169_RFIN1_HB3') OR InNet('RF_B1_PRX_MT6169_RFIP1_HB3') OR InNet('RF_B1_TRX_DPX') OR InNet('RF_B1_TRX_TXM') OR InNet('RF_B2_PA_DPX') OR InNet('RF_B2_PA_PA') OR InNet('RF_B2_PRX_DPX') OR InNet('RF_B2_PRX_SWITCH') OR InNet('RF_B2_TRX_DPX') OR InNet('RF_B2_TRX_TXM') OR InNet('RF_B2B3_PRX_BALUN') OR InNet('RF_B2B3_PRX_BALUN_RFIN1') OR InNet('RF_B2B3_PRX_BALUN_RFIP1') OR InNet('RF_B2B3_PRX_MT6169_RFIN1_MB2') OR InNet('RF_B2B3_PRX_MT6169_RFIP1_MB2') OR InNet('RF_B3_DRX_MT6169_RFIN2_MB1') OR InNet('RF_B3_DRX_MT6169_RFIP2_MB1') OR InNet('RF_B3_DRX_SAW') OR InNet('RF_B3_DRX_SAW_RFIN2') OR InNet('RF_B3_DRX_SAW_RFIP2') OR InNet('RF_B3_DRX_SWITCH') OR InNet('RF_B3_PA_DPX') OR InNet('RF_B3_PA_PA') OR InNet('RF_B3_PRX_DPX') OR InNet('RF_B3_PRX_SWITCH') OR InNet('RF_B3_TRX_DPX') OR InNet('RF_B3_TRX_TXM') OR InNet('RF_B34_PRX_SAW') OR InNet('RF_B34_PRX_TXM') OR InNet('RF_B34B39_PA_LPF_IN') OR InNet('RF_B34B39_PA_LPF_OUT') OR InNet('RF_B34B39_PA_PA') OR InNet('RF_B34B39_PA_TXM') OR InNet('RF_B34B39_PRX_MT6169_RFIN1_MB1') OR InNet('RF_B34B39_PRX_MT6169_RFIP1_MB1') OR InNet('RF_B34B39_PRX_SAW_RFIN1') OR InNet('RF_B34B39_PRX_SAW_RFIP1') OR InNet('RF_B39_DRX_MT6169_RFIN2_MB2') OR InNet('RF_B39_DRX_MT6169_RFIP2_MB2') OR InNet('RF_B39_DRX_SAW') OR InNet('RF_B39_DRX_SAW_RFIN2') OR InNet('RF_B39_DRX_SAW_RFIP2') OR InNet('RF_B39_DRX_SWITCH') OR InNet('RF_B39_PRX_SAW') OR InNet('RF_B39_PRX_TXM') OR InNet('RF_B40_DRX_SAW') OR InNet('RF_B40_DRX_SAW_1') OR InNet('RF_B40_DRX_SWITCH') OR InNet('RF_B40_DRX_SWITCH_1') OR InNet('RF_B40_TRX_1') OR InNet('RF_B40_TRX_BAW_IN') OR InNet('RF_B40_TRX_BAW_OUT') OR InNet('RF_B40_TRX_PA') OR InNet('RF_B40_TRX_TXM') OR InNet('RF_B40B41_PRX_BALUN') OR InNet('RF_B40B41_PRX_BALUN_RFIN1') OR InNet('RF_B40B41_PRX_BALUN_RFIP1') OR InNet('RF_B40B41_PRX_MT6169_RFIN1_HB1') OR InNet('RF_B40B41_PRX_MT6169_RFIP1_HB1') OR InNet('RF_B40B41_PRX_PA') OR InNet('RF_B40B41_PRX_PA_1') OR InNet('RF_B40B41_TRX_LPF_IN') OR InNet('RF_B40B41_TRX_LPF_OUT') OR InNet('RF_B40B41_TRX_PA_BYPASS') OR InNet('RF_B40B41_TRX_TXM_BYPASS') OR InNet('RF_B41_DRX_BALUN') OR InNet('RF_B41_DRX_BALUN_RFIN2') OR InNet('RF_B41_DRX_BALUN_RFIP2') OR InNet('RF_B41_DRX_MT6169_RFIN2_HB1') OR InNet('RF_B41_DRX_MT6169_RFIP2_HB1') OR InNet('RF_B41_DRX_SAW_IN_A') OR InNet('RF_B41_DRX_SAW_IN_B') OR InNet('RF_B41_DRX_SAW_OUT_A') OR InNet('RF_B41_DRX_SAW_OUT_B') OR InNet('RF_B41_DRX_SWITCH_A') OR InNet('RF_B41_DRX_SWITCH_A_1') OR InNet('RF_B41_DRX_SWITCH_B') OR InNet('RF_B41_DRX_SWITCH_B_1') OR InNet('RF_B41_TRX_FBAR_IN') OR InNet('RF_B41_TRX_FBAR_OUT') OR InNet('RF_B41_TRX_PA') OR InNet('RF_B41_TRX_TXM') OR InNet('RF_B5_DRX_MT6169_RFIN2_LB3') OR InNet('RF_B5_DRX_MT6169_RFIP2_LB3') OR InNet('RF_B5_DRX_SAW') OR InNet('RF_B5_DRX_SAW_RFIN2') OR InNet('RF_B5_DRX_SAW_RFIP2') OR InNet('RF_B5_DRX_SWITCH') OR InNet('RF_B5_PA_DPX') OR InNet('RF_B5_PA_PA') OR InNet('RF_B5_PRX_DPX_RFIN1') OR InNet('RF_B5_PRX_DPX_RFIP1') OR InNet('RF_B5_PRX_MT6169_RFIN1_LB3') OR InNet('RF_B5_PRX_MT6169_RFIP1_LB3') OR InNet('RF_B5_TRX_DPX') OR InNet('RF_B5_TRX_TXM') OR InNet('RF_B7_DRX_MT6169_RFIN2_HB2') OR InNet('RF_B7_DRX_MT6169_RFIP2_HB2') OR InNet('RF_B7_DRX_SAW') OR InNet('RF_B7_DRX_SAW_RFIN2') OR InNet('RF_B7_DRX_SAW_RFIP2') OR InNet('RF_B7_DRX_SWITCH') OR InNet('RF_B7_PA_PA') OR InNet('RF_B7_PRX_DPX_RFIN1') OR InNet('RF_B7_PRX_DPX_RFIP1') OR InNet('RF_B7_PRX_MT6169_RFIN1_HB2') OR InNet('RF_B7_PRX_MT6169_RFIP1_HB2') OR InNet('RF_B7_TRX_DPX') OR InNet('RF_B7_TRX_TXM') OR InNet('RF_BC0_PA_DPX') OR InNet('RF_BC0_PA_MT6158') OR InNet('RF_BC0_PA_MT6158_1') OR InNet('RF_BC0_PA_PA') OR InNet('RF_BC0_PA_PA_1') OR InNet('RF_BC0_PRX_DPX_LNA_LB_RXN') OR InNet('RF_BC0_PRX_DPX_LNA_LB_RXP') OR InNet('RF_BC0_PRX_MT6158_LNA_LB_RXN') OR InNet('RF_BC0_PRX_MT6158_LNA_LB_RXP') OR InNet('RF_BC0_TRX_ASM') OR InNet('RF_BC0_TRX_ASM_1') OR InNet('RF_BC0_TRX_DPX') OR InNet('RF_BC0_TX_MT6158') OR InNet('RF_BC0_TX_PA') OR InNet('RF_BC0_TX_PA_1') OR InNet('RF_GSM900_PRX_MT6169_RFIN1_LB1') OR InNet('RF_GSM900_PRX_MT6169_RFIP1_LB1') OR InNet('RF_GSM900_PRX_SAW') OR InNet('RF_GSM900_PRX_SAW_RFIN1') OR InNet('RF_GSM900_PRX_SAW_RFIP1') OR InNet('RF_GSM900_PRX_TXM') OR InNet('RF_HB_DRX_DIPLEXER') OR InNet('RF_HB1_TX_1') OR InNet('RF_HB1_TX_MT6169') OR InNet('RF_HB1_TX_PA') OR InNet('RF_HB2_TX_1') OR InNet('RF_HB2_TX_MT6169') OR InNet('RF_HB2_TX_PA') OR InNet('RF_LB3_TX_1') OR InNet('RF_LB3_TX_MT6169') OR InNet('RF_LB4_TX_1') OR InNet('RF_LB4_TX_MT6169') OR InNet('RF_LB4_TX_PA') OR InNet('RF_MB1_TX_1') OR InNet('RF_MB1_TX_MT6169') OR InNet('RF_MB1_TX_PA') OR InNet('RF_MB2_TX_1') OR InNet('RF_MB2_TX_MT6169') OR InNet('RF_MB2_TX_PA') OR InNet('RF_TXDET') OR InNet('RF_TXDET_MT6169') OR InNet('TCN') OR InNet('TCP') OR InNet('TDN0') OR InNet('TDN1') OR InNet('TDN2') OR InNet('TDN3') OR InNet('TDP0') OR InNet('TDP1') OR InNet('TDP2') OR InNet('TDP3') vs InNet('ADD1') OR InNet('ADD5') OR InNet('ADD6') OR InNet('C2K_ANTENNA') OR InNet('N15925478') OR InNet('N16931615') OR InNet('N16931617') OR InNet('N16931618') OR InNet('N16931625') OR InNet('N18263809') OR InNet('N19717773') OR InNet('N19780807') OR InNet('N19786985') OR InNet('N19787376') OR InNet('N19787407') OR InNet('N19789349') OR InNet('N19790693') OR InNet('N19790880') OR InNet('N19790902') OR InNet('N20607950') OR InNet('N47019540') OR InNet('N47019602') OR InNet('N48048238') OR InNet('N48113596') OR InNet('N48144087') OR InNet('N48144216') OR InNet('RCN') OR InNet('RCN_A') OR InNet('RCP') OR InNet('RCP_A') OR InNet('RDN0') OR InNet('RDN0_A') OR InNet('RDN1') OR InNet('RDN1_A') OR InNet('RDN2') OR InNet('RDN3') OR InNet('RDP0') OR InNet('RDP0_A') OR InNet('RDP1') OR InNet('RDP1_A') OR InNet('RDP2') OR InNet('RDP3') OR InNet('RF_ANT_DRX_SWITCH') OR InNet('RF_ANT_TRX_1') OR InNet('RF_ANT_TRX_2') OR InNet('RF_ANT_TRX_3') OR InNet('RF_ANT_TRX_4') OR InNet('RF_ANT_TRX_5') OR InNet('RF_ANT_TRX_ASM') OR InNet('RF_ANT_TRX_CARKIT') OR InNet('RF_ANT_TRX_TXM') OR InNet('RF_B1_DRX_MT6169_RFIN2_HB3') OR InNet('RF_B1_DRX_MT6169_RFIP2_HB3') OR InNet('RF_B1_DRX_SAW') OR InNet('RF_B1_DRX_SAW_RFIN2_HB1') OR InNet('RF_B1_DRX_SAW_RFIP2_HB1') OR InNet('RF_B1_DRX_SWITCH') OR InNet('RF_B1_PA_DPX') OR InNet('RF_B1_PA_PA') OR InNet('RF_B1_PRX_DPX_RFIN1') OR InNet('RF_B1_PRX_DPX_RFIP1') OR InNet('RF_B1_PRX_MT6169_RFIN1_HB3') OR InNet('RF_B1_PRX_MT6169_RFIP1_HB3') OR InNet('RF_B1_TRX_DPX') OR InNet('RF_B1_TRX_TXM') OR InNet('RF_B2_PA_DPX') OR InNet('RF_B2_PA_PA') OR InNet('RF_B2_PRX_DPX') OR InNet('RF_B2_PRX_SWITCH') OR InNet('RF_B2_TRX_DPX') OR InNet('RF_B2_TRX_TXM') OR InNet('RF_B2B3_PRX_BALUN') OR InNet('RF_B2B3_PRX_BALUN_RFIN1') OR InNet('RF_B2B3_PRX_BALUN_RFIP1') OR InNet('RF_B2B3_PRX_MT6169_RFIN1_MB2') OR InNet('RF_B2B3_PRX_MT6169_RFIP1_MB2') OR InNet('RF_B3_DRX_MT6169_RFIN2_MB1') OR InNet('RF_B3_DRX_MT6169_RFIP2_MB1') OR InNet('RF_B3_DRX_SAW') OR InNet('RF_B3_DRX_SAW_RFIN2') OR InNet('RF_B3_DRX_SAW_RFIP2') OR InNet('RF_B3_DRX_SWITCH') OR InNet('RF_B3_PA_DPX') OR InNet('RF_B3_PA_PA') OR InNet('RF_B3_PRX_DPX') OR InNet('RF_B3_PRX_SWITCH') OR InNet('RF_B3_TRX_DPX') OR InNet('RF_B3_TRX_TXM') OR InNet('RF_B34_PRX_SAW') OR InNet('RF_B34_PRX_TXM') OR InNet('RF_B34B39_PA_LPF_IN') OR InNet('RF_B34B39_PA_LPF_OUT') OR InNet('RF_B34B39_PA_PA') OR InNet('RF_B34B39_PA_TXM') OR InNet('RF_B34B39_PRX_MT6169_RFIN1_MB1') OR InNet('RF_B34B39_PRX_MT6169_RFIP1_MB1') OR InNet('RF_B34B39_PRX_SAW_RFIN1') OR InNet('RF_B34B39_PRX_SAW_RFIP1') OR InNet('RF_B39_DRX_MT6169_RFIN2_MB2') OR InNet('RF_B39_DRX_MT6169_RFIP2_MB2') OR InNet('RF_B39_DRX_SAW') OR InNet('RF_B39_DRX_SAW_RFIN2') OR InNet('RF_B39_DRX_SAW_RFIP2') OR InNet('RF_B39_DRX_SWITCH') OR InNet('RF_B39_PRX_SAW') OR InNet('RF_B39_PRX_TXM') OR InNet('RF_B40_DRX_SAW') OR InNet('RF_B40_DRX_SAW_1') OR InNet('RF_B40_DRX_SWITCH') OR InNet('RF_B40_DRX_SWITCH_1') OR InNet('RF_B40_TRX_1') OR InNet('RF_B40_TRX_BAW_IN') OR InNet('RF_B40_TRX_BAW_OUT') OR InNet('RF_B40_TRX_PA') OR InNet('RF_B40_TRX_TXM') OR InNet('RF_B40B41_PRX_BALUN') OR InNet('RF_B40B41_PRX_BALUN_RFIN1') OR InNet('RF_B40B41_PRX_BALUN_RFIP1') OR InNet('RF_B40B41_PRX_MT6169_RFIN1_HB1') OR InNet('RF_B40B41_PRX_MT6169_RFIP1_HB1') OR InNet('RF_B40B41_PRX_PA') OR InNet('RF_B40B41_PRX_PA_1') OR InNet('RF_B40B41_TRX_LPF_IN') OR InNet('RF_B40B41_TRX_LPF_OUT') OR InNet('RF_B40B41_TRX_PA_BYPASS') OR InNet('RF_B40B41_TRX_TXM_BYPASS') OR InNet('RF_B41_DRX_BALUN') OR InNet('RF_B41_DRX_BALUN_RFIN2') OR InNet('RF_B41_DRX_BALUN_RFIP2') OR InNet('RF_B41_DRX_MT6169_RFIN2_HB1') OR InNet('RF_B41_DRX_MT6169_RFIP2_HB1') OR InNet('RF_B41_DRX_SAW_IN_A') OR InNet('RF_B41_DRX_SAW_IN_B') OR InNet('RF_B41_DRX_SAW_OUT_A') OR InNet('RF_B41_DRX_SAW_OUT_B') OR InNet('RF_B41_DRX_SWITCH_A') OR InNet('RF_B41_DRX_SWITCH_A_1') OR InNet('RF_B41_DRX_SWITCH_B') OR InNet('RF_B41_DRX_SWITCH_B_1') OR InNet('RF_B41_TRX_FBAR_IN') OR InNet('RF_B41_TRX_FBAR_OUT') OR InNet('RF_B41_TRX_PA') OR InNet('RF_B41_TRX_TXM') OR InNet('RF_B5_DRX_MT6169_RFIN2_LB3') OR InNet('RF_B5_DRX_MT6169_RFIP2_LB3') OR InNet('RF_B5_DRX_SAW') OR InNet('RF_B5_DRX_SAW_RFIN2') OR InNet('RF_B5_DRX_SAW_RFIP2') OR InNet('RF_B5_DRX_SWITCH') OR InNet('RF_B5_PA_DPX') OR InNet('RF_B5_PA_PA') OR InNet('RF_B5_PRX_DPX_RFIN1') OR InNet('RF_B5_PRX_DPX_RFIP1') OR InNet('RF_B5_PRX_MT6169_RFIN1_LB3') OR InNet('RF_B5_PRX_MT6169_RFIP1_LB3') OR InNet('RF_B5_TRX_DPX') OR InNet('RF_B5_TRX_TXM') OR InNet('RF_B7_DRX_MT6169_RFIN2_HB2') OR InNet('RF_B7_DRX_MT6169_RFIP2_HB2') OR InNet('RF_B7_DRX_SAW') OR InNet('RF_B7_DRX_SAW_RFIN2') OR InNet('RF_B7_DRX_SAW_RFIP2') OR InNet('RF_B7_DRX_SWITCH') OR InNet('RF_B7_PA_PA') OR InNet('RF_B7_PRX_DPX_RFIN1') OR InNet('RF_B7_PRX_DPX_RFIP1') OR InNet('RF_B7_PRX_MT6169_RFIN1_HB2') OR InNet('RF_B7_PRX_MT6169_RFIP1_HB2') OR InNet('RF_B7_TRX_DPX') OR InNet('RF_B7_TRX_TXM') OR InNet('RF_BC0_PA_DPX') OR InNet('RF_BC0_PA_MT6158') OR InNet('RF_BC0_PA_MT6158_1') OR InNet('RF_BC0_PA_PA') OR InNet('RF_BC0_PA_PA_1') OR InNet('RF_BC0_PRX_DPX_LNA_LB_RXN') OR InNet('RF_BC0_PRX_DPX_LNA_LB_RXP') OR InNet('RF_BC0_PRX_MT6158_LNA_LB_RXN') OR InNet('RF_BC0_PRX_MT6158_LNA_LB_RXP') OR InNet('RF_BC0_TRX_ASM') OR InNet('RF_BC0_TRX_ASM_1') OR InNet('RF_BC0_TRX_DPX') OR InNet('RF_BC0_TX_MT6158') OR InNet('RF_BC0_TX_PA') OR InNet('RF_BC0_TX_PA_1') OR InNet('RF_GSM900_PRX_MT6169_RFIN1_LB1') OR InNet('RF_GSM900_PRX_MT6169_RFIP1_LB1') OR InNet('RF_GSM900_PRX_SAW') OR InNet('RF_GSM900_PRX_SAW_RFIN1') OR InNet('RF_GSM900_PRX_SAW_RFIP1') OR InNet('RF_GSM900_PRX_TXM') OR InNet('RF_HB_DRX_DIPLEXER') OR InNet('RF_HB1_TX_1') OR InNet('RF_HB1_TX_MT6169') OR InNet('RF_HB1_TX_PA') OR InNet('RF_HB2_TX_1') OR InNet('RF_HB2_TX_MT6169') OR InNet('RF_HB2_TX_PA') OR InNet('RF_LB3_TX_1') OR InNet('RF_LB3_TX_MT6169') OR InNet('RF_LB4_TX_1') OR InNet('RF_LB4_TX_MT6169') OR InNet('RF_LB4_TX_PA') OR InNet('RF_MB1_TX_1') OR InNet('RF_MB1_TX_MT6169') OR InNet('RF_MB1_TX_PA') OR InNet('RF_MB2_TX_1') OR InNet('RF_MB2_TX_MT6169') OR InNet('RF_MB2_TX_PA') OR InNet('RF_TXDET') OR InNet('RF_TXDET_MT6169') OR InNet('TCN') OR InNet('TCP') OR InNet('TDN0') OR InNet('TDN1') OR InNet('TDN2') OR InNet('TDN3') OR InNet('TDP0') OR InNet('TDP1') OR InNet('TDP2') OR InNet('TDP3')] p1: holewidth=12 width=20 viastyle="Through Hole" minholewidth=12 minwidth=20 maxholewidth=12 maxwidth=20
RoutingVias "RoutingVias - Default - DEFAULT" [All] p2: holewidth=12 width=20 viastyle="Through Hole" minholewidth=12 minwidth=20 maxholewidth=12 maxwidth=20
SMDToCorner "SMDToCorner - Default - DEFAULT" [All] p1: distance=0
SolderMaskExpansion "SolderMaskExpansion from CAM settings" [All] p1: expansion=2
Width "Width - Net - D_GND - 90OHM_1" [InNet('D_GND') And OnLayer('Bottom')] p1: maxlimit=0 minlimit=99999 preferedwidth=0 toplayer_minwidth=0 midlayer1_minwidth=0 midlayer2_minwidth=0 midlayer3_minwidth=0 midlayer4_minwidth=0 bottomlayer_minwidth=0 minimp=50.000000 maximp=50.000000 favimp=50.000000
Width "Width - Net - D_GND - 90OHM" [InNet('D_GND') And OnLayer('Inner Layer 4')] p2: maxlimit=0 minlimit=99999 preferedwidth=0 toplayer_minwidth=0 midlayer1_minwidth=0 midlayer2_minwidth=0 midlayer3_minwidth=0 midlayer4_minwidth=0 bottomlayer_minwidth=0 minimp=50.000000 maximp=50.000000 favimp=50.000000
Width "Width - Net - D_GND - 100OHM_1" [InNet('D_GND')] p3: maxlimit=0 minlimit=99999 preferedwidth=0 toplayer_minwidth=0 midlayer1_minwidth=0 midlayer2_minwidth=0 midlayer3_minwidth=0 midlayer4_minwidth=0 bottomlayer_minwidth=0 minimp=50.000000 maximp=50.000000 favimp=50.000000
Width "Width - Net - D_GND - 90OHM_2" [InNet('D_GND') And OnLayer('Top')] p4: maxlimit=0 minlimit=99999 preferedwidth=0 toplayer_minwidth=0 midlayer1_minwidth=0 midlayer2_minwidth=0 midlayer3_minwidth=0 midlayer4_minwidth=0 bottomlayer_minwidth=0 minimp=50.000000 maximp=50.000000 favimp=50.000000
Width "Width - Net - D_GND - 50OHM_3" [InNet('D_GND') And OnLayer('Bottom')] p5: maxlimit=0 minlimit=99999 preferedwidth=0 toplayer_minwidth=0 midlayer1_minwidth=0 midlayer2_minwidth=0 midlayer3_minwidth=0 midlayer4_minwidth=0 bottomlayer_minwidth=0 minimp=50.000000 maximp=50.000000 favimp=50.000000
Width "Width - Net - D_GND - 50OHM" [InNet('D_GND') And OnLayer('Inner Layer 2')] p6: maxlimit=0 minlimit=99999 preferedwidth=0 toplayer_minwidth=0 midlayer1_minwidth=0 midlayer2_minwidth=0 midlayer3_minwidth=0 midlayer4_minwidth=0 bottomlayer_minwidth=0 minimp=50.000000 maximp=50.000000 favimp=50.000000
Width "Width - Net - D_GND - 50OHM_1" [InNet('D_GND') And OnLayer('Inner Layer 5')] p7: maxlimit=0 minlimit=99999 preferedwidth=0 toplayer_minwidth=0 midlayer1_minwidth=0 midlayer2_minwidth=0 midlayer3_minwidth=0 midlayer4_minwidth=0 bottomlayer_minwidth=0 minimp=50.000000 maximp=50.000000 favimp=50.000000
Width "Width - Net - D_GND - 50OHM_2" [InNet('D_GND') And OnLayer('Top')] p8: maxlimit=0 minlimit=99999 preferedwidth=0 toplayer_minwidth=0 midlayer1_minwidth=0 midlayer2_minwidth=0 midlayer3_minwidth=0 midlayer4_minwidth=0 bottomlayer_minwidth=0 minimp=50.000000 maximp=50.000000 favimp=50.000000
Width "Width - Net - D_GND - 100OHM" [InNet('D_GND') And OnLayer('Bottom')] p9: maxlimit=0 minlimit=99999 preferedwidth=0 toplayer_minwidth=0 midlayer1_minwidth=0 midlayer2_minwidth=0 midlayer3_minwidth=0 midlayer4_minwidth=0 bottomlayer_minwidth=0 minimp=50.000000 maximp=50.000000 favimp=50.000000
Width "Width - Net - D_GND - 90OHM_3" [InNet('D_GND')] p10: maxlimit=0 minlimit=99999 preferedwidth=0 toplayer_minwidth=0 midlayer1_minwidth=0 midlayer2_minwidth=0 midlayer3_minwidth=0 midlayer4_minwidth=0 bottomlayer_minwidth=0 minimp=50.000000 maximp=50.000000 favimp=50.000000
Width "Width - NetClass - 100OHM" [InNetClass('100OHM') And OnLayer('Top')] p11: maxlimit=200 minlimit=3 preferedwidth=4
Width "Width - NetClass - 90OHM_1" [InNetClass('90OHM') And OnLayer('Bottom')] p12: maxlimit=200 minlimit=3 preferedwidth=5
Width "Width - NetClass - RF50(L3)" [InNetClass('RF50(L3)') And OnLayer('Top') OR InNetClass('RF50(L3)') And OnLayer('Bottom')] p13: maxlimit=200 minlimit=4 preferedwidth=10
Width "Width - NetClass - 90OHM" [InNetClass('90OHM') And OnLayer('Inner Layer 4')] p14: maxlimit=200 minlimit=3 preferedwidth=3.5
Width "Width - NetClass - 50OHM" [InNetClass('50OHM') And OnLayer('Inner Layer 2') OR InNetClass('100OHM') And OnLayer('Inner Layer 4') OR InNetClass('50OHM') And OnLayer('Inner Layer 5')] p15: maxlimit=200 minlimit=3 preferedwidth=3
Width "Width - NetClass - 50OHM_1" [InNetClass('50OHM') And OnLayer('Top') OR InNetClass('90OHM') And OnLayer('Top') OR InNetClass('50OHM') And OnLayer('Bottom')] p16: maxlimit=200 minlimit=4 preferedwidth=5
Width "Default Width" [All] p17: maxlimit=200 minlimit=4 preferedwidth=4
20 further rules are at their usual default settings.

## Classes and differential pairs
net class 100OHM: RCN RCN_A RCP RCP_A RDN0 RDN0_A RDN1 RDN1_A RDN2 RDN3 RDP0 RDP0_A RDP1 RDP1_A RDP2 RDP3 RF_B1_DRX_MT6169_RFIN2_HB3 RF_B1_DRX_MT6169_RFIP2_HB3 RF_B1_DRX_SAW_RFIN2_HB1 RF_B1_DRX_SAW_RFIP2_HB1 RF_B1_PRX_DPX_RFIN1 RF_B1_PRX_DPX_RFIP1 RF_B1_PRX_MT6169_RFIN1_HB3 RF_B1_PRX_MT6169_RFIP1_HB3 RF_B2B3_PRX_BALUN_RFIN1 RF_B2B3_PRX_BALUN_RFIP1 RF_B2B3_PRX_MT6169_RFIN1_MB2 RF_B2B3_PRX_MT6169_RFIP1_MB2 RF_B3_DRX_MT6169_RFIN2_MB1 RF_B3_DRX_MT6169_RFIP2_MB1 RF_B3_DRX_SAW_RFIN2 RF_B3_DRX_SAW_RFIP2 RF_B5_DRX_MT6169_RFIN2_LB3 RF_B5_DRX_MT6169_RFIP2_LB3 RF_B5_DRX_SAW_RFIN2 RF_B5_DRX_SAW_RFIP2 RF_B5_PRX_DPX_RFIN1 RF_B5_PRX_DPX_RFIP1 RF_B5_PRX_MT6169_RFIN1_LB3 RF_B5_PRX_MT6169_RFIP1_LB3 RF_B7_DRX_MT6169_RFIN2_HB2 RF_B7_DRX_MT6169_RFIP2_HB2 RF_B7_DRX_SAW_RFIN2 RF_B7_DRX_SAW_RFIP2 RF_B7_PRX_DPX_RFIN1 RF_B7_PRX_DPX_RFIP1 RF_B7_PRX_MT6169_RFIN1_HB2 RF_B7_PRX_MT6169_RFIP1_HB2 RF_B34B39_PRX_MT6169_RFIN1_MB1 RF_B34B39_PRX_MT6169_RFIP1_MB1 RF_B34B39_PRX_SAW_RFIN1 RF_B34B39_PRX_SAW_RFIP1 RF_B39_DRX_MT6169_RFIN2_MB2 RF_B39_DRX_MT6169_RFIP2_MB2 RF_B39_DRX_SAW_RFIN2 RF_B39_DRX_SAW_RFIP2 RF_B40B41_PRX_BALUN_RFIN1 RF_B40B41_PRX_BALUN_RFIP1 RF_B40B41_PRX_MT6169_RFIN1_HB1 RF_B40B41_PRX_MT6169_RFIP1_HB1 RF_B41_DRX_BALUN_RFIN2 RF_B41_DRX_BALUN_RFIP2 RF_B41_DRX_MT6169_RFIN2_HB1 RF_B41_DRX_MT6169_RFIP2_HB1 RF_BC0_PRX_DPX_LNA_LB_RXN RF_BC0_PRX_DPX_LNA_LB_RXP RF_BC0_PRX_MT6158_LNA_LB_RXN RF_BC0_PRX_MT6158_LNA_LB_RXP RF_GSM900_PRX_MT6169_RFIN1_LB1 RF_GSM900_PRX_MT6169_RFIP1_LB1 RF_GSM900_PRX_SAW_RFIN1 RF_GSM900_PRX_SAW_RFIP1 TCN TCP TDN0 TDN1 TDN2 TDN3 TDP0 TDP1 TDP2 TDP3
net class 50OHM: ADD1 ADD5 ADD6 C2K_ANTENNA N15925478 N16931615 N16931617 N16931618 N16931625 N18263809 N19717773 N19780807 N19786985 N19787376 N19787407 N19789349 N19790693 N19790880 N19790902 N20607950 N47019540 N47019602 N48048238 N48113596 N48144087 N48144216 RF_ANT_DRX_SWITCH RF_ANT_TRX_1 RF_ANT_TRX_2 RF_ANT_TRX_3 RF_ANT_TRX_4 RF_ANT_TRX_5 RF_ANT_TRX_ASM RF_ANT_TRX_CARKIT RF_ANT_TRX_TXM RF_B1_DRX_SAW RF_B1_DRX_SWITCH RF_B1_PA_DPX RF_B1_PA_PA RF_B1_TRX_DPX RF_B1_TRX_TXM RF_B2_PA_DPX RF_B2_PA_PA RF_B2_PRX_DPX RF_B2_PRX_SWITCH RF_B2_TRX_DPX RF_B2_TRX_TXM RF_B2B3_PRX_BALUN RF_B3_DRX_SAW RF_B3_DRX_SWITCH RF_B3_PA_DPX RF_B3_PA_PA RF_B3_PRX_DPX RF_B3_PRX_SWITCH RF_B3_TRX_DPX RF_B3_TRX_TXM RF_B5_DRX_SAW RF_B5_DRX_SWITCH RF_B5_PA_DPX RF_B5_PA_PA RF_B5_TRX_DPX RF_B5_TRX_TXM RF_B7_DRX_SAW RF_B7_DRX_SWITCH RF_B7_PA_PA RF_B7_TRX_DPX RF_B7_TRX_TXM RF_B34_PRX_SAW RF_B34_PRX_TXM RF_B34B39_PA_LPF_IN RF_B34B39_PA_LPF_OUT RF_B34B39_PA_PA RF_B34B39_PA_TXM RF_B39_DRX_SAW RF_B39_DRX_SWITCH RF_B39_PRX_SAW RF_B39_PRX_TXM RF_B40_DRX_SAW RF_B40_DRX_SAW_1 RF_B40_DRX_SWITCH RF_B40_DRX_SWITCH_1 RF_B40_TRX_1 RF_B40_TRX_BAW_IN RF_B40_TRX_BAW_OUT RF_B40_TRX_PA RF_B40_TRX_TXM RF_B40B41_PRX_BALUN RF_B40B41_PRX_PA RF_B40B41_PRX_PA_1 RF_B40B41_TRX_LPF_IN RF_B40B41_TRX_LPF_OUT RF_B40B41_TRX_PA_BYPASS RF_B40B41_TRX_TXM_BYPASS RF_B41_DRX_BALUN RF_B41_DRX_SAW_IN_A RF_B41_DRX_SAW_IN_B RF_B41_DRX_SAW_OUT_A RF_B41_DRX_SAW_OUT_B RF_B41_DRX_SWITCH_A RF_B41_DRX_SWITCH_A_1 RF_B41_DRX_SWITCH_B RF_B41_DRX_SWITCH_B_1 RF_B41_TRX_FBAR_IN RF_B41_TRX_FBAR_OUT RF_B41_TRX_PA RF_B41_TRX_TXM RF_BC0_PA_DPX RF_BC0_PA_MT6158 RF_BC0_PA_MT6158_1 RF_BC0_PA_PA RF_BC0_PA_PA_1 RF_BC0_TRX_ASM RF_BC0_TRX_ASM_1 RF_BC0_TRX_DPX RF_BC0_TX_MT6158 RF_BC0_TX_PA RF_BC0_TX_PA_1 RF_GSM900_PRX_SAW RF_GSM900_PRX_TXM RF_HB1_TX_1 RF_HB1_TX_MT6169 RF_HB1_TX_PA RF_HB2_TX_1 RF_HB2_TX_MT6169 RF_HB2_TX_PA RF_HB_DRX_DIPLEXER RF_LB3_TX_1 RF_LB3_TX_MT6169 RF_LB4_TX_1 RF_LB4_TX_MT6169 RF_LB4_TX_PA RF_MB1_TX_1 RF_MB1_TX_MT6169 RF_MB1_TX_PA RF_MB2_TX_1 RF_MB2_TX_MT6169 RF_MB2_TX_PA RF_TXDET RF_TXDET_MT6169
net class 90OHM: USB_DM USB_DP
net class RF50(L3): GPS_ANT GPS_RF_LNA N16931626 N17415034 N17416996 N35189484 N35189587 N35190588 N35190689 RF_WBT RF_WF_5G WB_ANT

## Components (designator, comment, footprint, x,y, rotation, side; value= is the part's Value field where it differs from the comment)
ANT3604 "ANT$2F$2P$2F$SMD$2F$PVT1024" ANT$2F$2P$2F$SMD$2F$PVT1024 2441.31,4910.09 r270 bottom
ANT3605 "ANT$2F$2P$2F$SMD$2F$PVT1024" ANT$2F$2P$2F$SMD$2F$PVT1024 2559.31,4910.09 r270 bottom
ANT3606 "ANT$2F$2P$2F$SMD$2F$PVT1024" ANT$2F$2P$2F$SMD$2F$PVT1024 2324.31,4910.09 r270 bottom
ANT3607 "ANT$2F$2P$2F$SMD$2F$PVT1024" ANT$2F$2P$2F$SMD$2F$PVT1024 1644.95,393.83 r0 top
ANT3608 "ANT$2F$2P$2F$SMD$2F$PVT1024" ANT$2F$2P$2F$SMD$2F$PVT1024 184.95,393.49 r0 top
ANT3609 "ANT$2F$2P$2F$SMD$2F$PVT1024" ANT$2F$2P$2F$SMD$2F$PVT1024 1002.95,393.83 r0 top
ANT3610 "ANT$2F$2P$2F$SMD$2F$PVT1024" ANT$2F$2P$2F$SMD$2F$PVT1024 2237.3,358.09 r0 top
ANT3611 "ANT$2F$2P$2F$SMD$2F$P25$2F$3X3" ANT$2F$2P$2F$SMD$2F$P25$2F$3X3 876.08,69.11 r0 bottom
ANT5001 "ANT$2F$2P$2F$SMD$2F$PVT1024" ANT$2F$2P$2F$SMD$2F$PVT1024 529.31,4949.09 r270 bottom
ANT5002 "ANT$2F$2P$2F$SMD$2F$PVT1024" ANT$2F$2P$2F$SMD$2F$PVT1024 293.31,4949.09 r270 bottom
ANT5003 "ANT$2F$2P$2F$SMD$2F$PVT1024" ANT$2F$2P$2F$SMD$2F$PVT1024 411.31,4949.09 r270 bottom
ANT5004 "ANT$2F$2P$2F$SMD$2F$PVT1024" ANT$2F$2P$2F$SMD$2F$PVT1024 373.95,4585.83 r0 top
ANT5101 "PAD$2F$1P$2F$R2.2" PAD$2F$1P$2F$R2.2 280.08,2270.49 r90 bottom
ANT5102 "PAD$2F$1P$2F$R2.2" PAD$2F$1P$2F$R2.2 280.08,2390.49 r90 bottom
BEAD5001 "BEAD0402" BEAD0402 869.31,4559.09 r180 top
BEAD6001 "BEAD0603" BEAD0603 161.95,2831.49 r90 bottom
BEAD6002 "BEAD0603" BEAD0603 519.95,2926.83 r270 top
BEAD6003 "BEAD0603" BEAD0603 438.95,3223.49 r270 bottom
BEAD6004 "BEAD0603" BEAD0603 592.95,2875.83 r180 top
BEAD6005 "BEAD0603" BEAD0603 388.95,3223.49 r270 bottom
C1101 "C0201" C0201 447.81,3718.33 r90 top
C1102 "C0201" C0201 457.81,3818.33 r180 top
C1103 "C0402" C0402 452.81,3773.33 r90 top
C1104 "C0201" C0201 1496.3,3807.09 r90 top
C1105 "C0201" C0201 1593.31,3850.09 r90 top
C1106 "C0201" C0201 1547.31,3802.09 r270 top
C2007 "C0603" C0603 1489.31,3005.09 r0 top
C2008 "C0603" C0603 527.56,3322.5 r90 top
C2011 "C0402" C0402 1112.95,3125.83 r90 top
C2012 "C0402" C0402 1127.95,3059.83 r0 top
C2013 "C0402" C0402 1114.31,2979.09 r0 top
C2014 "C0402" C0402 1136.95,3233.83 r90 top
C2015 "C0402" C0402 1089.45,3322.49 r90 top
C2016 "C0402" C0402 901.95,3372.83 r90 top
C2017 "C0402" C0402 693.31,3185.09 r0 top
C2018 "C0402" C0402 743.95,3045.83 r180 top
C2019 "C0402" C0402 706.31,3102.09 r180 top
C2020 "C0402" C0402 848.95,3414.49 r90 top
C2022 "C0201" C0201 1013.31,2910.65 r270 top
C2023 "C0201" C0201 829.31,2958.09 r180 top
C2027 "C0402" C0402 983.31,2911.09 r270 top
C2030 "C0201" C0201 896.95,3318.49 r270 top
C2031 "C0201" C0201 780.95,3283.49 r180 top
C2032 "C0201" C0201 748.31,3156.09 r180 top
C2033 "C0201" C0201 743.95,3221.83 r270 top
C2034 "C0201" C0201 743.31,3307.09 r90 top
C2036 "C0201" C0201 767.31,2962.09 r270 top
C2038 "C0402" C0402 1000.31,2972.15 r0 top
C2039 "C0603" C0603 1203.31,3457.09 r0 top
C2040 "C0603" C0603 1182.31,3384.09 r270 top
C2041 "C0201" C0201 826.95,3353.49 r90 top
C2042 "C0201" C0201 700.31,2964.09 r90 top
C2043 "C0201" C0201 1055.81,2910.65 r0 top
C2044 "C0201" C0201 722.31,2964.09 r90 top
C2046 "C0201" C0201 1383.31,3686.09 r90 bottom
C2047 "C0201" C0201 918.31,3318.09 r270 top
C2048 "C0201" C0201 770.31,3005.09 r180 top
C2051 "C0201" C0201 857.95,3344.49 r180 top
C2054 "C0201" C0201 938.31,3293.09 r0 bottom
C2055 "C0402" C0402 1273.95,2987.49 r90 top
C2056 "C0201" C0201 747.31,2962.09 r270 top
C2057 "C0201" C0201 780.95,3262.49 r180 top
C2058 "C0402" C0402 1304.95,2987.49 r270 top
C2101 "C0603" C0603 396.31,3764.09 r270 bottom
C2312 "C0402" C0402 382.95,2579.49 r0 top
C2315 "C0201" C0201 493.95,2645.49 r0 top
C2319 "C0603" C0603 506.31,2730.09 r0 top
C2320 "C0402" C0402 147.95,3710.49 r180 bottom
C2322 "C0402" C0402 232.95,3559.49 r90 bottom
C2323 "C0201" C0201 229.95,3495.49 r270 bottom
C2402 "C0402" C0402 774.31,3467.09 r180 bottom
C2403 "C0402" C0402 1378.31,2860.09 r180 top
C2411 "C0603" C0603 669.31,3450.09 r0 bottom
C2412 "C0402" C0402 1429.31,2940.09 r90 top
C2413 "C0201" C0201 684.31,3599.09 r270 bottom
C3101 "C0201" C0201 1783.15,3843.09 r180 top
C3102 "C0201" C0201 1862.65,3850.59 r0 bottom
C3103 "C0201" C0201 1895.65,4055.59 r90 top
C3104 "C0201" C0201 1955.65,3826.59 r270 bottom
C3105 "C0201" C0201 1773.15,3993.09 r90 top
C3106 "C0201" C0201 1793.15,3993.09 r90 top
C3108 "C0201" C0201 1858.65,4050.59 r180 top
C3109 "C0201" C0201 1813.65,4050.59 r180 top
C3110 "C0201" C0201 1861.65,4101.09 r90 top
C3112 "C0201" C0201 1814.65,3870.59 r180 bottom
C3116 "C0201" C0201 1824.65,3905.59 r90 bottom
C3205 "C0201" C0201 2050.65,3495.59 r270 bottom
C3206 "C0201" C0201 2065.65,3460.59 r0 bottom
C3207 "C0201" C0201 2015.65,3690.59 r270 bottom
C3210 "C0201" C0201 1980.65,3705.59 r180 bottom
C3211 "C0201" C0201 1980.65,3680.59 r180 bottom
C3215 "C0201" C0201 2075.65,3650.59 r180 bottom
C3216 "C0201" C0201 2060.65,3615.59 r90 bottom
C3217 "C0201" C0201 1850.65,3705.59 r90 top
C3222 "C0201" C0201 2075.65,3700.59 r180 bottom
C3223 "C0201" C0201 2040.65,3690.59 r90 bottom
C3225 "C0201" C0201 1825.65,3705.59 r90 top
C3226 "C0201" C0201 1825.65,3635.59 r270 top
C3228 "C0201" C0201 1815.65,3600.59 r0 top
C3233 "C0201" C0201 2080.65,3570.59 r90 bottom
C3239 "C0603" C0603 1887.89,2911.81 r0 top
C3241 "C0201" C0201 1845.65,3495.59 r180 bottom
C3242 "C0201" C0201 2075.65,3495.59 r270 bottom
C3243 "C0201" C0201 2055.65,3570.59 r90 bottom
C3244 "C0201" C0201 2105.65,3570.59 r90 bottom
C3245 "C0201" C0201 2105.65,3525.59 r270 bottom
C3248 "C0201" C0201 1830.65,3535.59 r90 bottom
C3249 "C0201" C0201 1855.65,3535.59 r90 bottom
C3250 "C0201" C0201 1820.65,3440.59 r270 top
C3251 "C0201" C0201 1805.65,3475.59 r180 top
C3252 "C0201" C0201 1820.65,3535.59 r90 top
C3254 "C0201" C0201 1840.65,3670.59 r0 top
C3255 "C0201" C0201 2140.65,3580.59 r90 bottom
C3256 "C0201" C0201 1845.65,3535.59 r270 top
C3257 "C0201" C0201 1945.65,3690.59 r90 bottom
C3258 "C0201" C0201 1910.65,3450.59 r0 top
C3259 "C0201" C0201 1920.65,3500.59 r180 top
C3260 "C0201" C0201 1910.65,3705.59 r0 bottom
C3261 "C0201" C0201 1890.65,3370.59 r0 bottom
C3262 "C0201" C0201 2110.65,3435.59 r90 top
C3263 "C0201" C0201 1970.65,3390.59 r90 top
C3264 "C0201" C0201 2110.65,3390.59 r270 top
C3265 "C0201" C0201 2020.65,3390.59 r270 top
C3271 "C0201" C0201 2100.65,3470.59 r180 top
C3272 "C0201" C0201 1935.65,3390.59 r90 top
C3273 "C0201" C0201 1910.65,3425.59 r180 top
C3276 "C0201" C0201 2140.65,3395.59 r90 bottom
C3285 "C0201" C0201 2065.65,3505.59 r90 top
C3286 "C0201" C0201 2075.65,3540.59 r0 top
C3288 "C0201" C0201 2030.65,3540.59 r0 top
C3289 "C0201" C0201 2125.65,3465.59 r270 bottom
C3290 "C0201" C0201 1513.15,2863.09 r270 top
C3291 "C0201" C0201 1819.08,3000.58 r0 top
C3302 "C0201" C0201 2255.65,3895.59 r180 top
C3303 "C0201" C0201 2355.65,3860.59 r90 top
C3304 "C0201" C0201 2258.65,3388.59 r270 top
C3307 "C0201" C0201 2095.65,3905.59 r180 top
C3310 "C0201" C0201 2361.65,3693.59 r270 top
C3311 "C0201" C0201 2095.65,3880.59 r180 top
C3312 "C0201" C0201 2215.65,3830.59 r0 top
C3313 "C0201" C0201 2160.65,3845.59 r90 top
C3314 "C0201" C0201 1800.65,3380.59 r90 top
C3315 "C0201" C0201 2070.65,3780.59 r180 top
C3316 "C0201" C0201 2285.65,3825.59 r180 top
C3317 "C0201" C0201 2145.65,3725.59 r180 top
C3318 "C0201" C0201 2333.3,3163.09 r0 top
C3321 "C0201" C0201 2105.65,3795.59 r90 top
C3323 "C0201" C0201 2103.65,3930.59 r180 top
C3324 "C0201" C0201 2340.65,3425.59 r0 top
C3325 "C0201" C0201 2103.65,3955.59 r180 top
C3327 "C0201" C0201 2095.65,3830.59 r180 top
C3328 "C0201" C0201 1910.65,3655.59 r90 top
C3330 "C0201" C0201 2200.65,3730.59 r90 top
C3331 "C0201" C0201 1870.65,3535.59 r90 top
C3334 "C0201" C0201 1790.65,3695.59 r0 top
C3335 "C0201" C0201 2095.65,3855.59 r180 top
C3336 "C0201" C0201 1935.65,3655.59 r90 top
C3339 "C0603" C0603 2320.65,3385.59 r180 top
C3340 "C0201" C0201 2241.65,3423.59 r0 top
C3341 "C0201" C0201 2010.65,3705.59 r90 top
C3342 "C0201" C0201 2050.65,3590.59 r180 top
C3343 "C0201" C0201 2085.65,3615.59 r180 top
C3344 "C0201" C0201 2035.65,3705.59 r90 top
C3348 "C0201" C0201 2295.65,3425.59 r180 top
C3349 "C0201" C0201 1960.65,3695.59 r90 top
C3352 "C0201" C0201 1983.15,3565.59 r90 top
C3353 "C0201" C0201 1985.65,3695.59 r90 top
C3361 "C0201" C0201 2235.65,3735.59 r0 top
C3362 "C0201" C0201 2235.65,3710.59 r0 top
C3383 "C0201" C0201 1186.65,2901.09 r0 top
C3401 "C0201" C0201 1950.65,4080.59 r270 top
C3405 "C0201" C0201 1925.65,4080.59 r270 top
C3407 "C0201" C0201 2285.65,3995.59 r0 top
C3412 "C0201" C0201 2050.65,4080.59 r270 top
C3413 "C0201" C0201 2000.65,4080.59 r270 top
C3414 "C0201" C0201 1959.15,4003.59 r90 bottom
C3415 "C0201" C0201 1919.15,4003.59 r90 bottom
C3416 "C0201" C0201 2025.65,4080.59 r270 top
C3417 "C0201" C0201 1975.65,4080.59 r270 top
C3418 "C0201" C0201 2164.15,4088.59 r90 bottom
C3419 "C0201" C0201 2100.65,4055.59 r180 top
C3420 "C0201" C0201 2100.65,4030.59 r180 top
C3421 "C0201" C0201 2191.65,4163.59 r90 top
C3432 "C0201" C0201 2226.65,4021.09 r0 bottom
C3433 "C0201" C0201 2114.15,4168.59 r180 top
C3434 "C0201" C0201 2202.65,4112.59 r0 top
C3435 "C0201" C0201 2071.65,3976.09 r180 bottom
C3436 "C0201" C0201 2256.65,4087.59 r180 top
C3438 "C0201" C0201 2071.65,4001.09 r0 bottom
C3439 "C0201" C0201 2071.65,4026.09 r0 bottom
C3447 "C0201" C0201 2071.65,4051.09 r0 bottom
C3453 "C0201" C0201 2115.65,3980.59 r180 top
C3454 "C0201" C0201 2115.65,4005.59 r180 top
C3455 "C0201" C0201 2228.31,4160.65 r180 bottom
C3456 "C0201" C0201 2303.65,4045.59 r180 top
C3457 "C0201" C0201 2285.65,4020.59 r180 top
C3458 "C0201" C0201 2004.15,4008.59 r90 bottom
C3459 "C0201" C0201 2029.15,4008.59 r90 bottom
C3460 "L0201" L0201 2071.65,4106.09 r180 bottom
C3499 "C0201" C0201 2254.15,3993.59 r180 bottom
C3601 "C0402" C0402 311.53,607.69 r180 bottom
C3602 "C0402" C0402 2137.95,4502.83 r0 bottom
C3603 "C0402" C0402 227.31,621.09 r90 bottom
C3604 "C0402" C0402 2039.3,4702.09 r0 bottom
C3702 "C0402" C0402 1810.31,4367.09 r270 top
C3703 "C0201" C0201 1748.95,4473.49 r180 top
C3704 "C0402" C0402 1923.3,4367.09 r270 top
C3705 "C0201" C0201 1758.95,4576.49 r270 top
C3706 "C0402" C0402 1739.31,4658.09 r90 top
C3707 "C0201" C0201 1748.95,4494.49 r180 top
C3709 "C0201" C0201 1964.31,4384.09 r0 top
C3710 "C0201" C0201 1941.17,4613.13 r90 top
C3801 "C0201" C0201 2165.95,4309.83 r0 bottom
C3802 "C0201" C0201 2145.31,4513.09 r180 top
C3805 "C0201" C0201 2145.31,4489.09 r180 top
C3806 "C0201" C0201 2137.31,4665.09 r180 top
C3807 "C0201" C0201 1984.95,4592.49 r270 top
C3808 "C0201" C0201 2006.95,4592.49 r270 top
C3901 "C0201" C0201 1934.08,4250.11 r270 bottom
C3902 "C0201" C0201 1913.08,4250.11 r270 bottom
C3903 "C0201" C0201 1892.08,4250.11 r270 bottom
C3904 "C0201" C0201 1986.08,4262.11 r180 bottom
C3905 "C0402" C0402 2026.08,4306.11 r90 bottom
C3906 "C0201" C0201 2028.08,4252.11 r270 bottom
C3907 "C0402" C0402 1949.31,4443.09 r90 bottom
C3908 "C0402" C0402 2026.08,4372.11 r270 bottom
C3909 "C0201" C0201 2003.08,4429.11 r90 bottom
C3910 "C0201" C0201 2026.08,4429.11 r90 bottom
C3911 "C0402" C0402 1756.31,2739.56 r180 top
C3912 "C0201" C0201 1808.31,2766.56 r270 top
C3913 "C0201" C0201 1851.95,2864.96 r90 top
